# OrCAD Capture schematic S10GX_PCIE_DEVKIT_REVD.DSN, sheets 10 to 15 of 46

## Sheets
10 S10 GX Bank 3I,J,K,L: size C
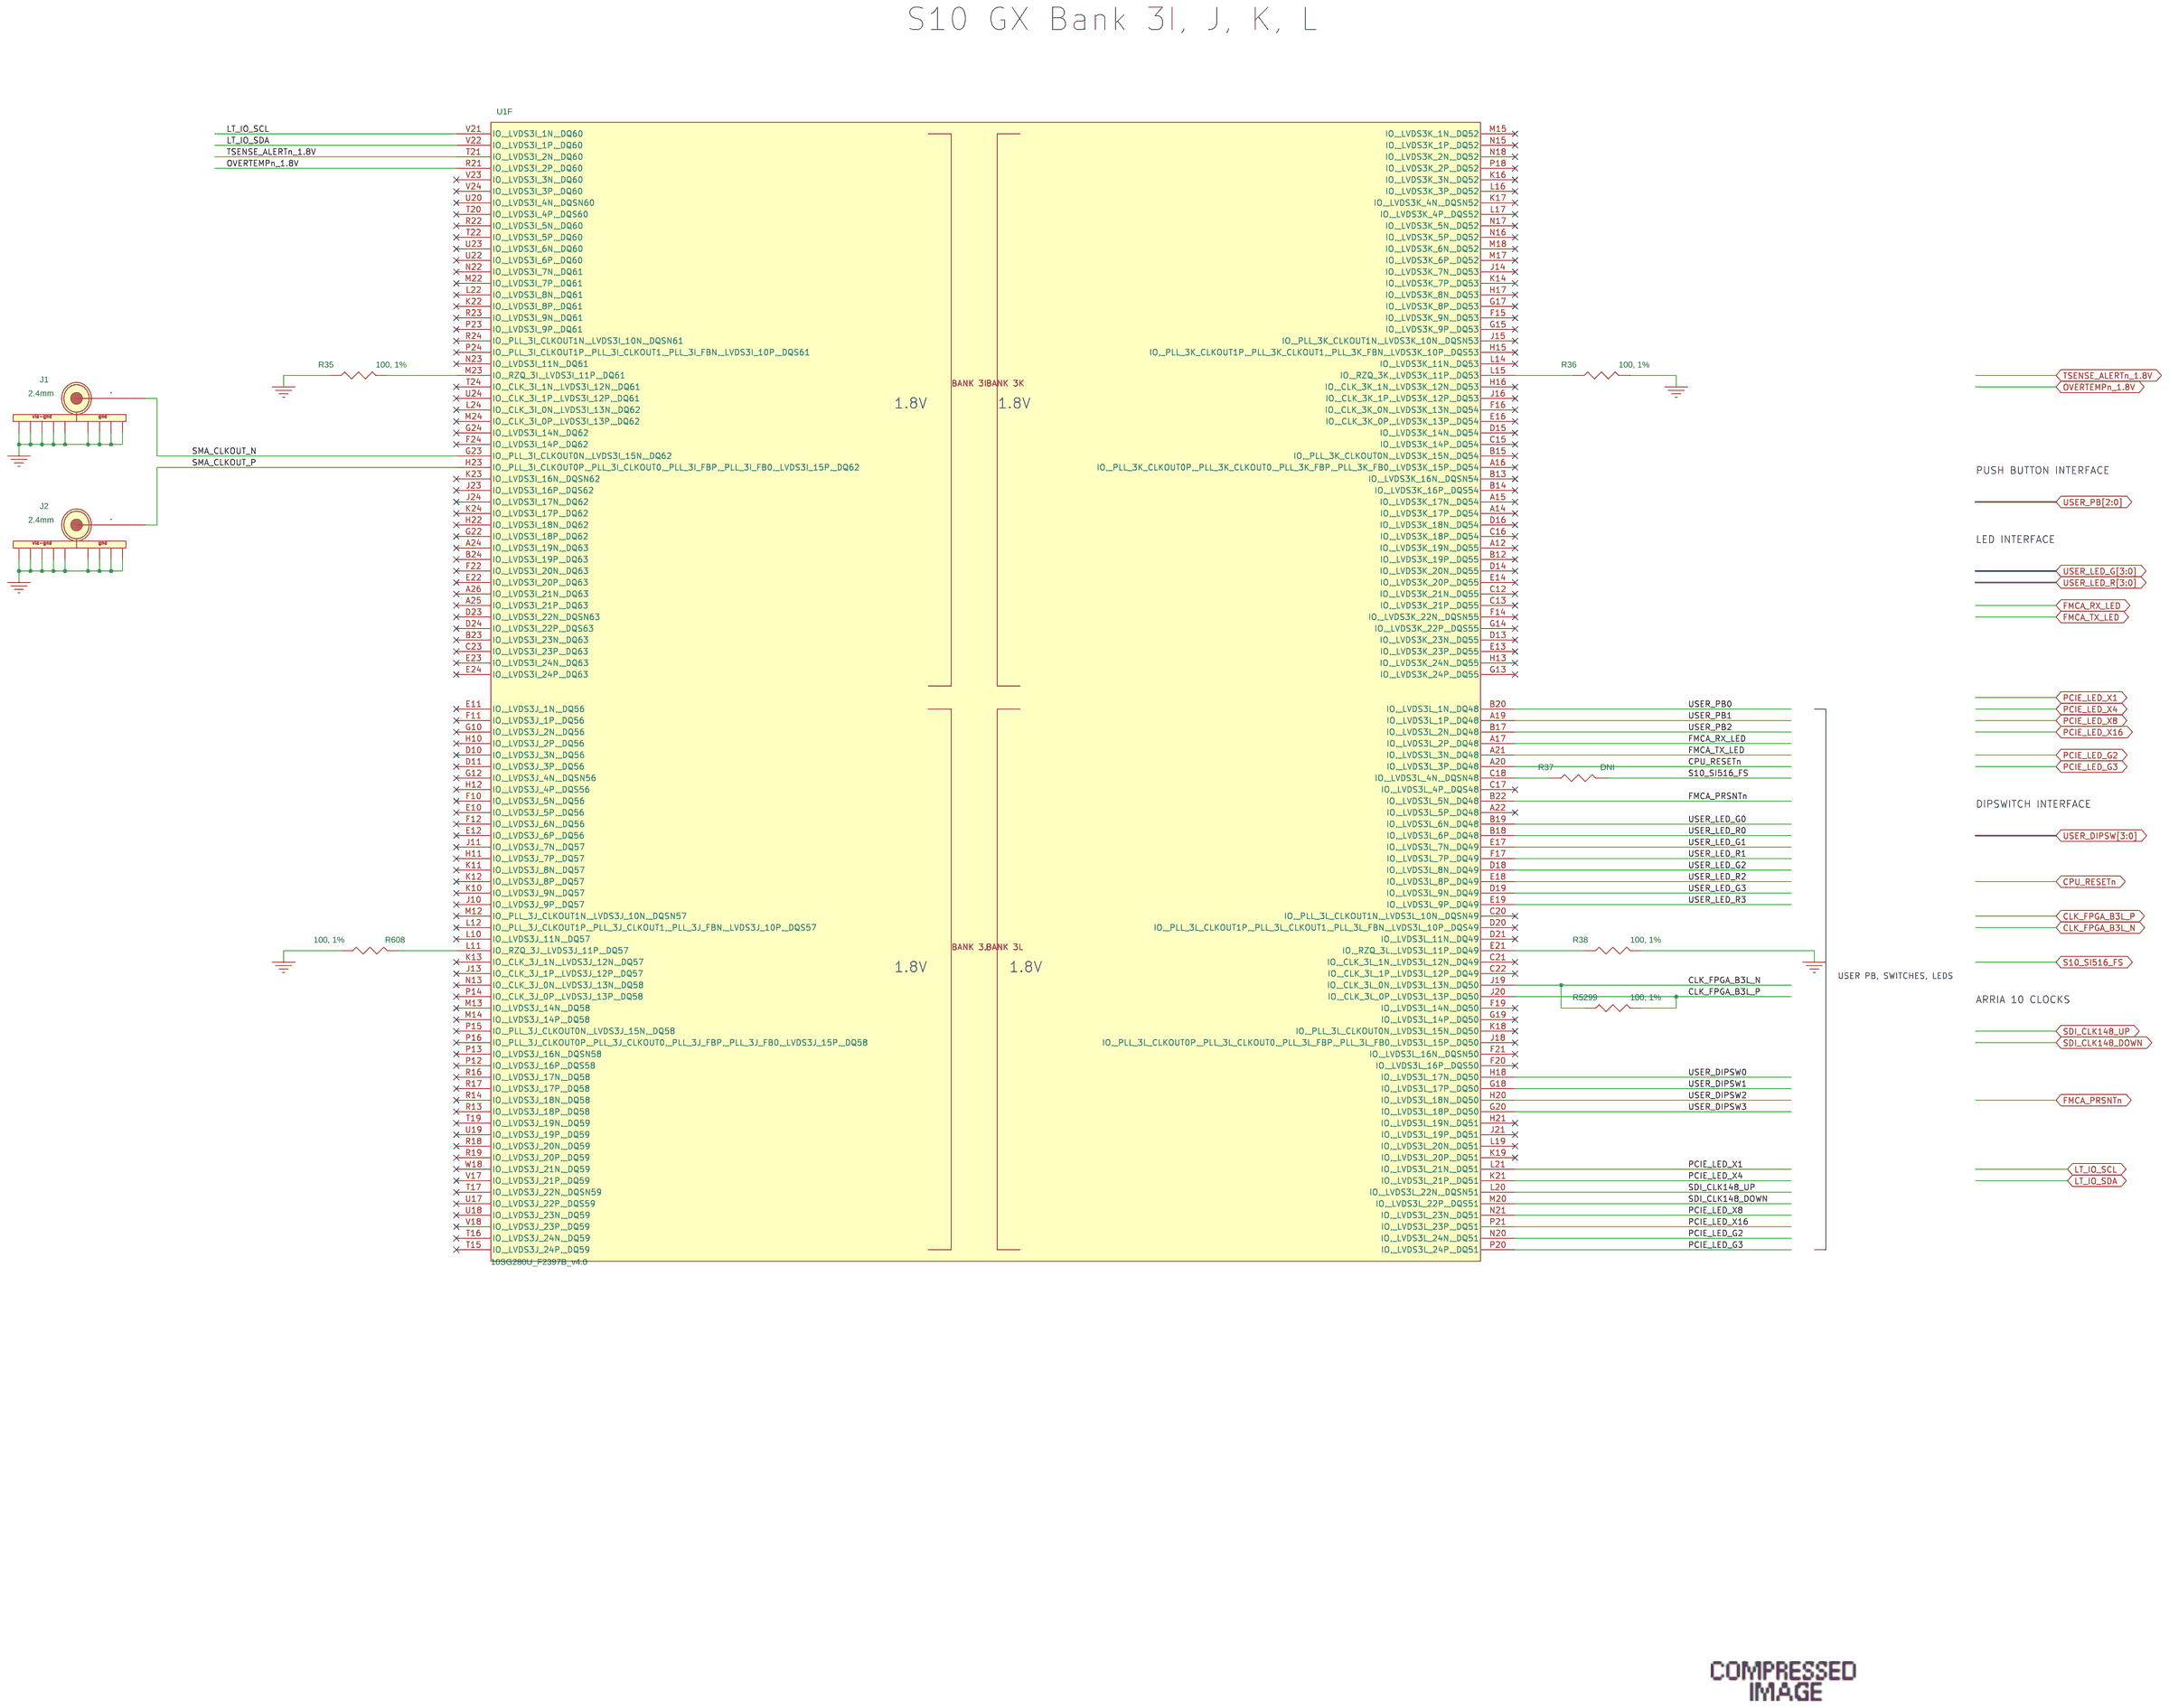
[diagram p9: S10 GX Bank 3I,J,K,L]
11 S10 GX Xcvr GXBL 1C,D,E,F: size C
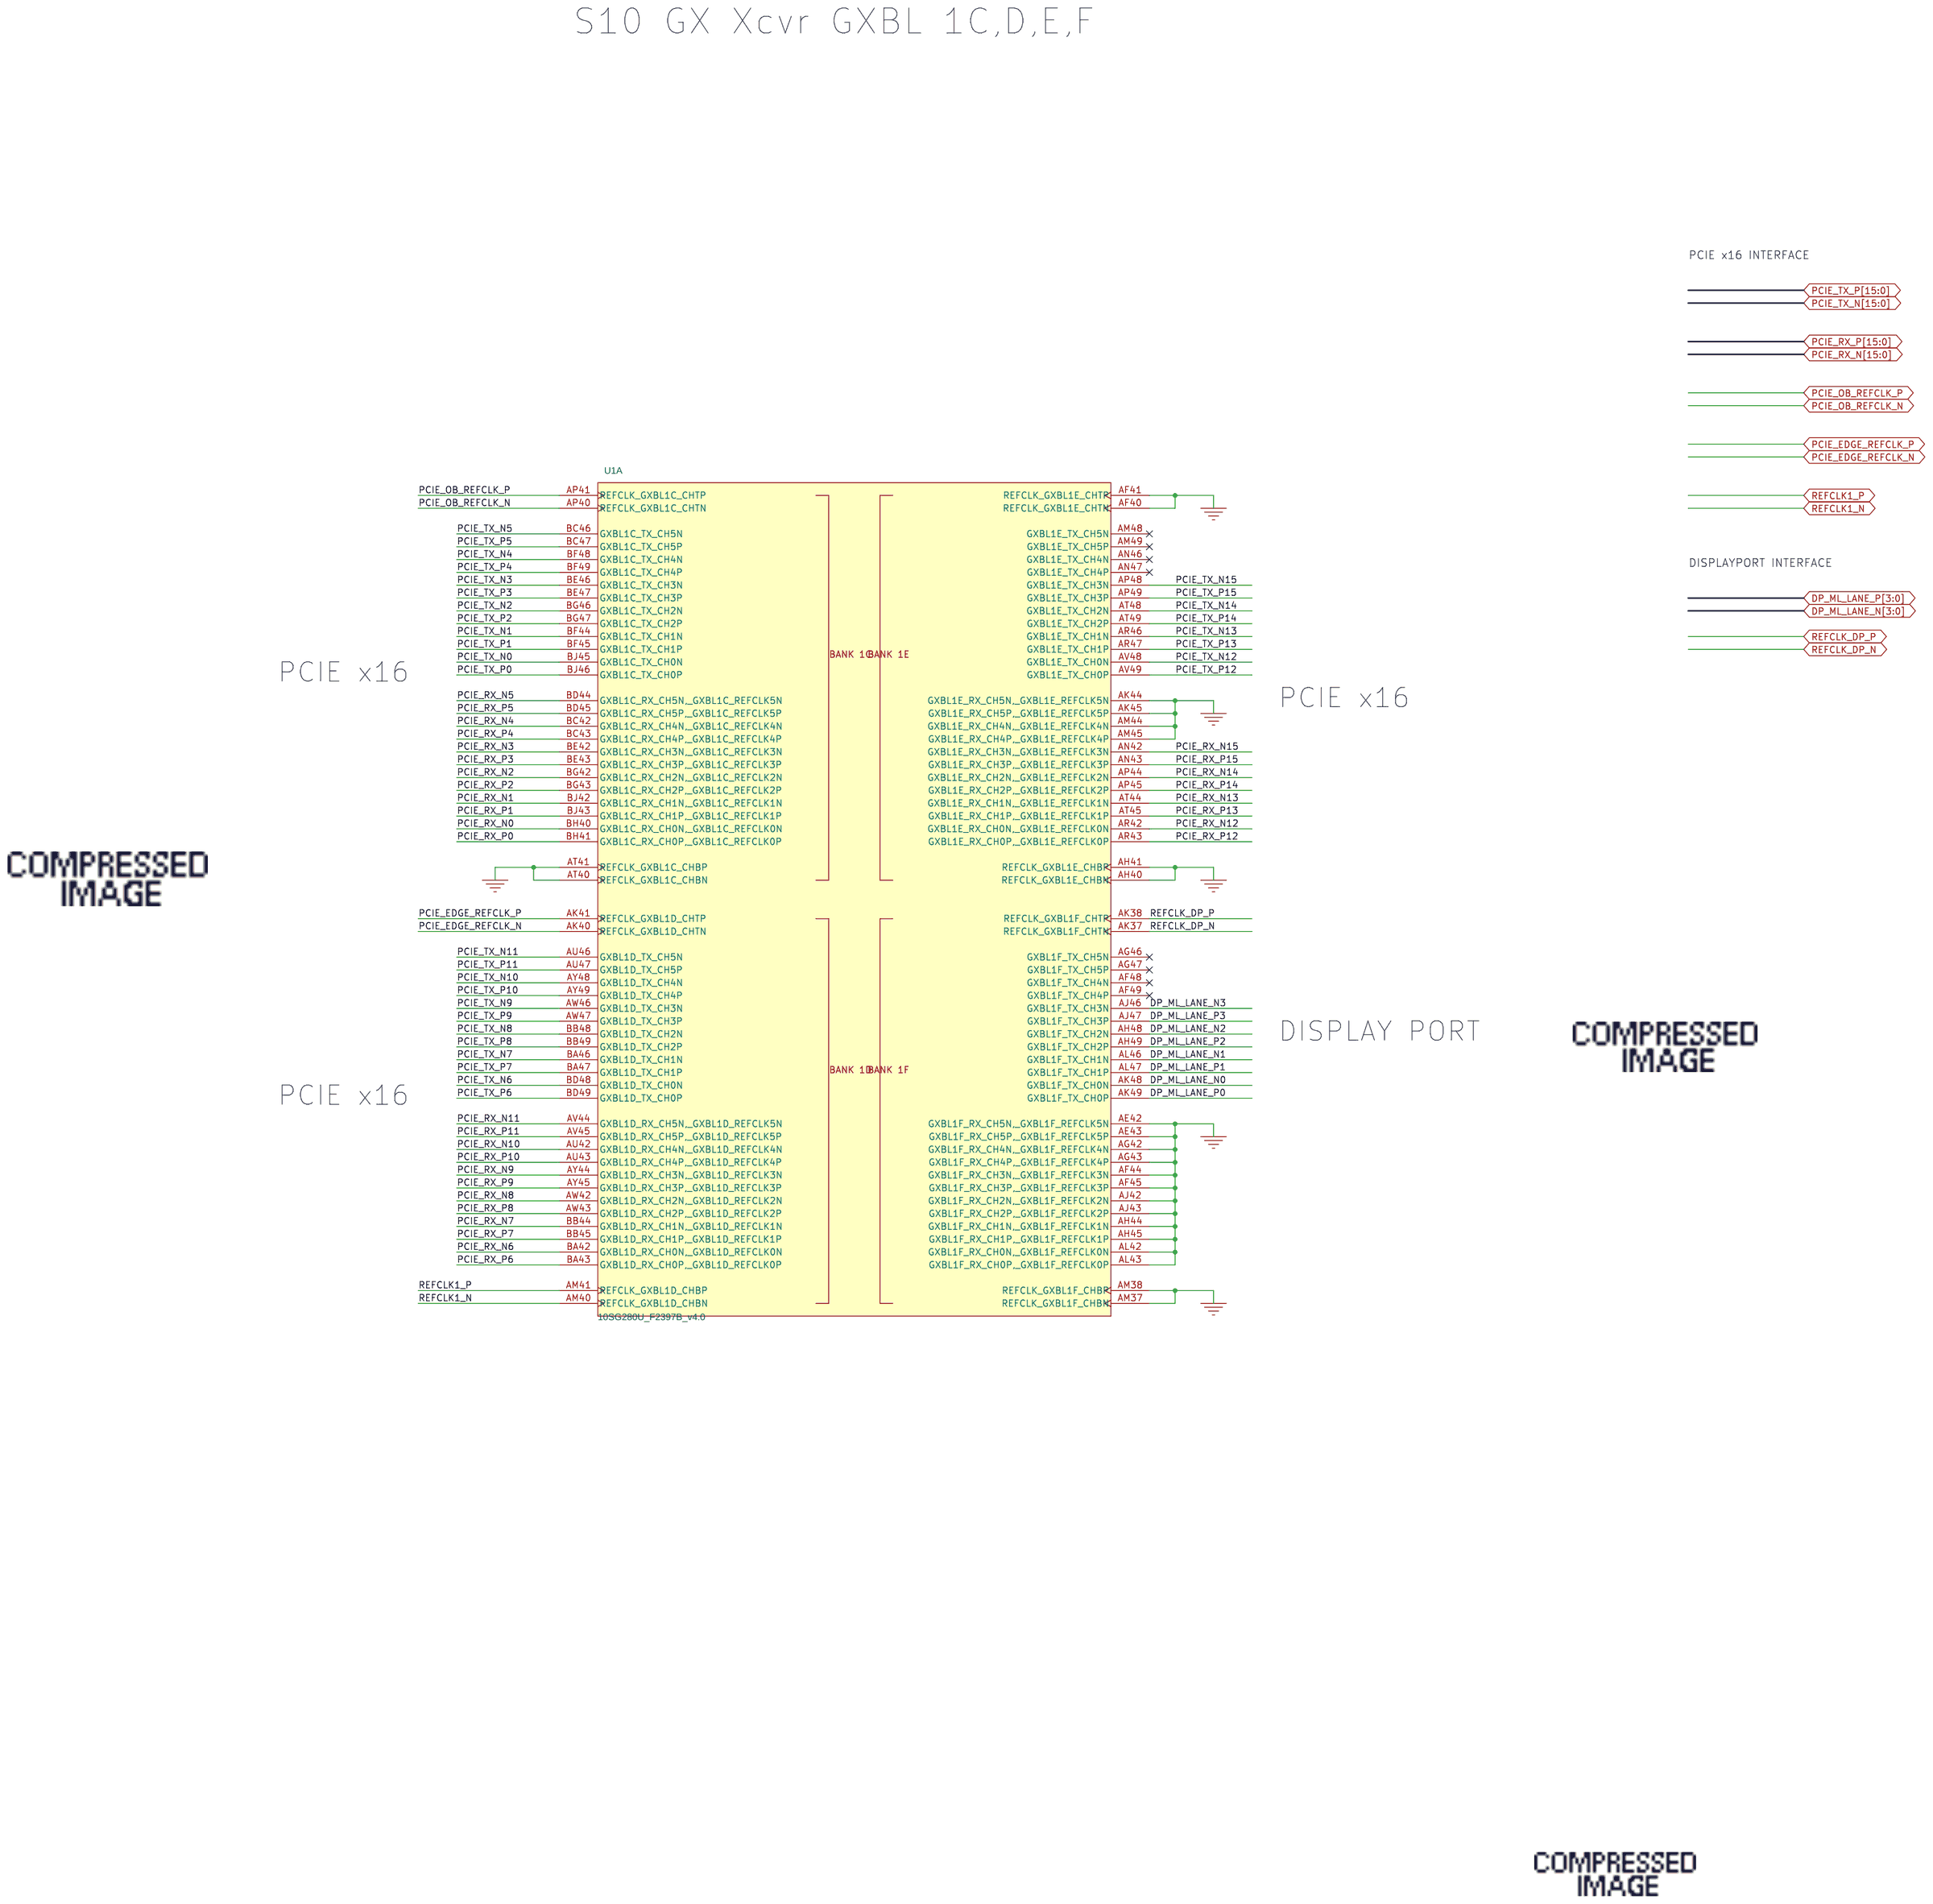
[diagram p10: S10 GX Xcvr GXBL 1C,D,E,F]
12 S10 GX Xcvr GXBL 1K,L,M,N: size C
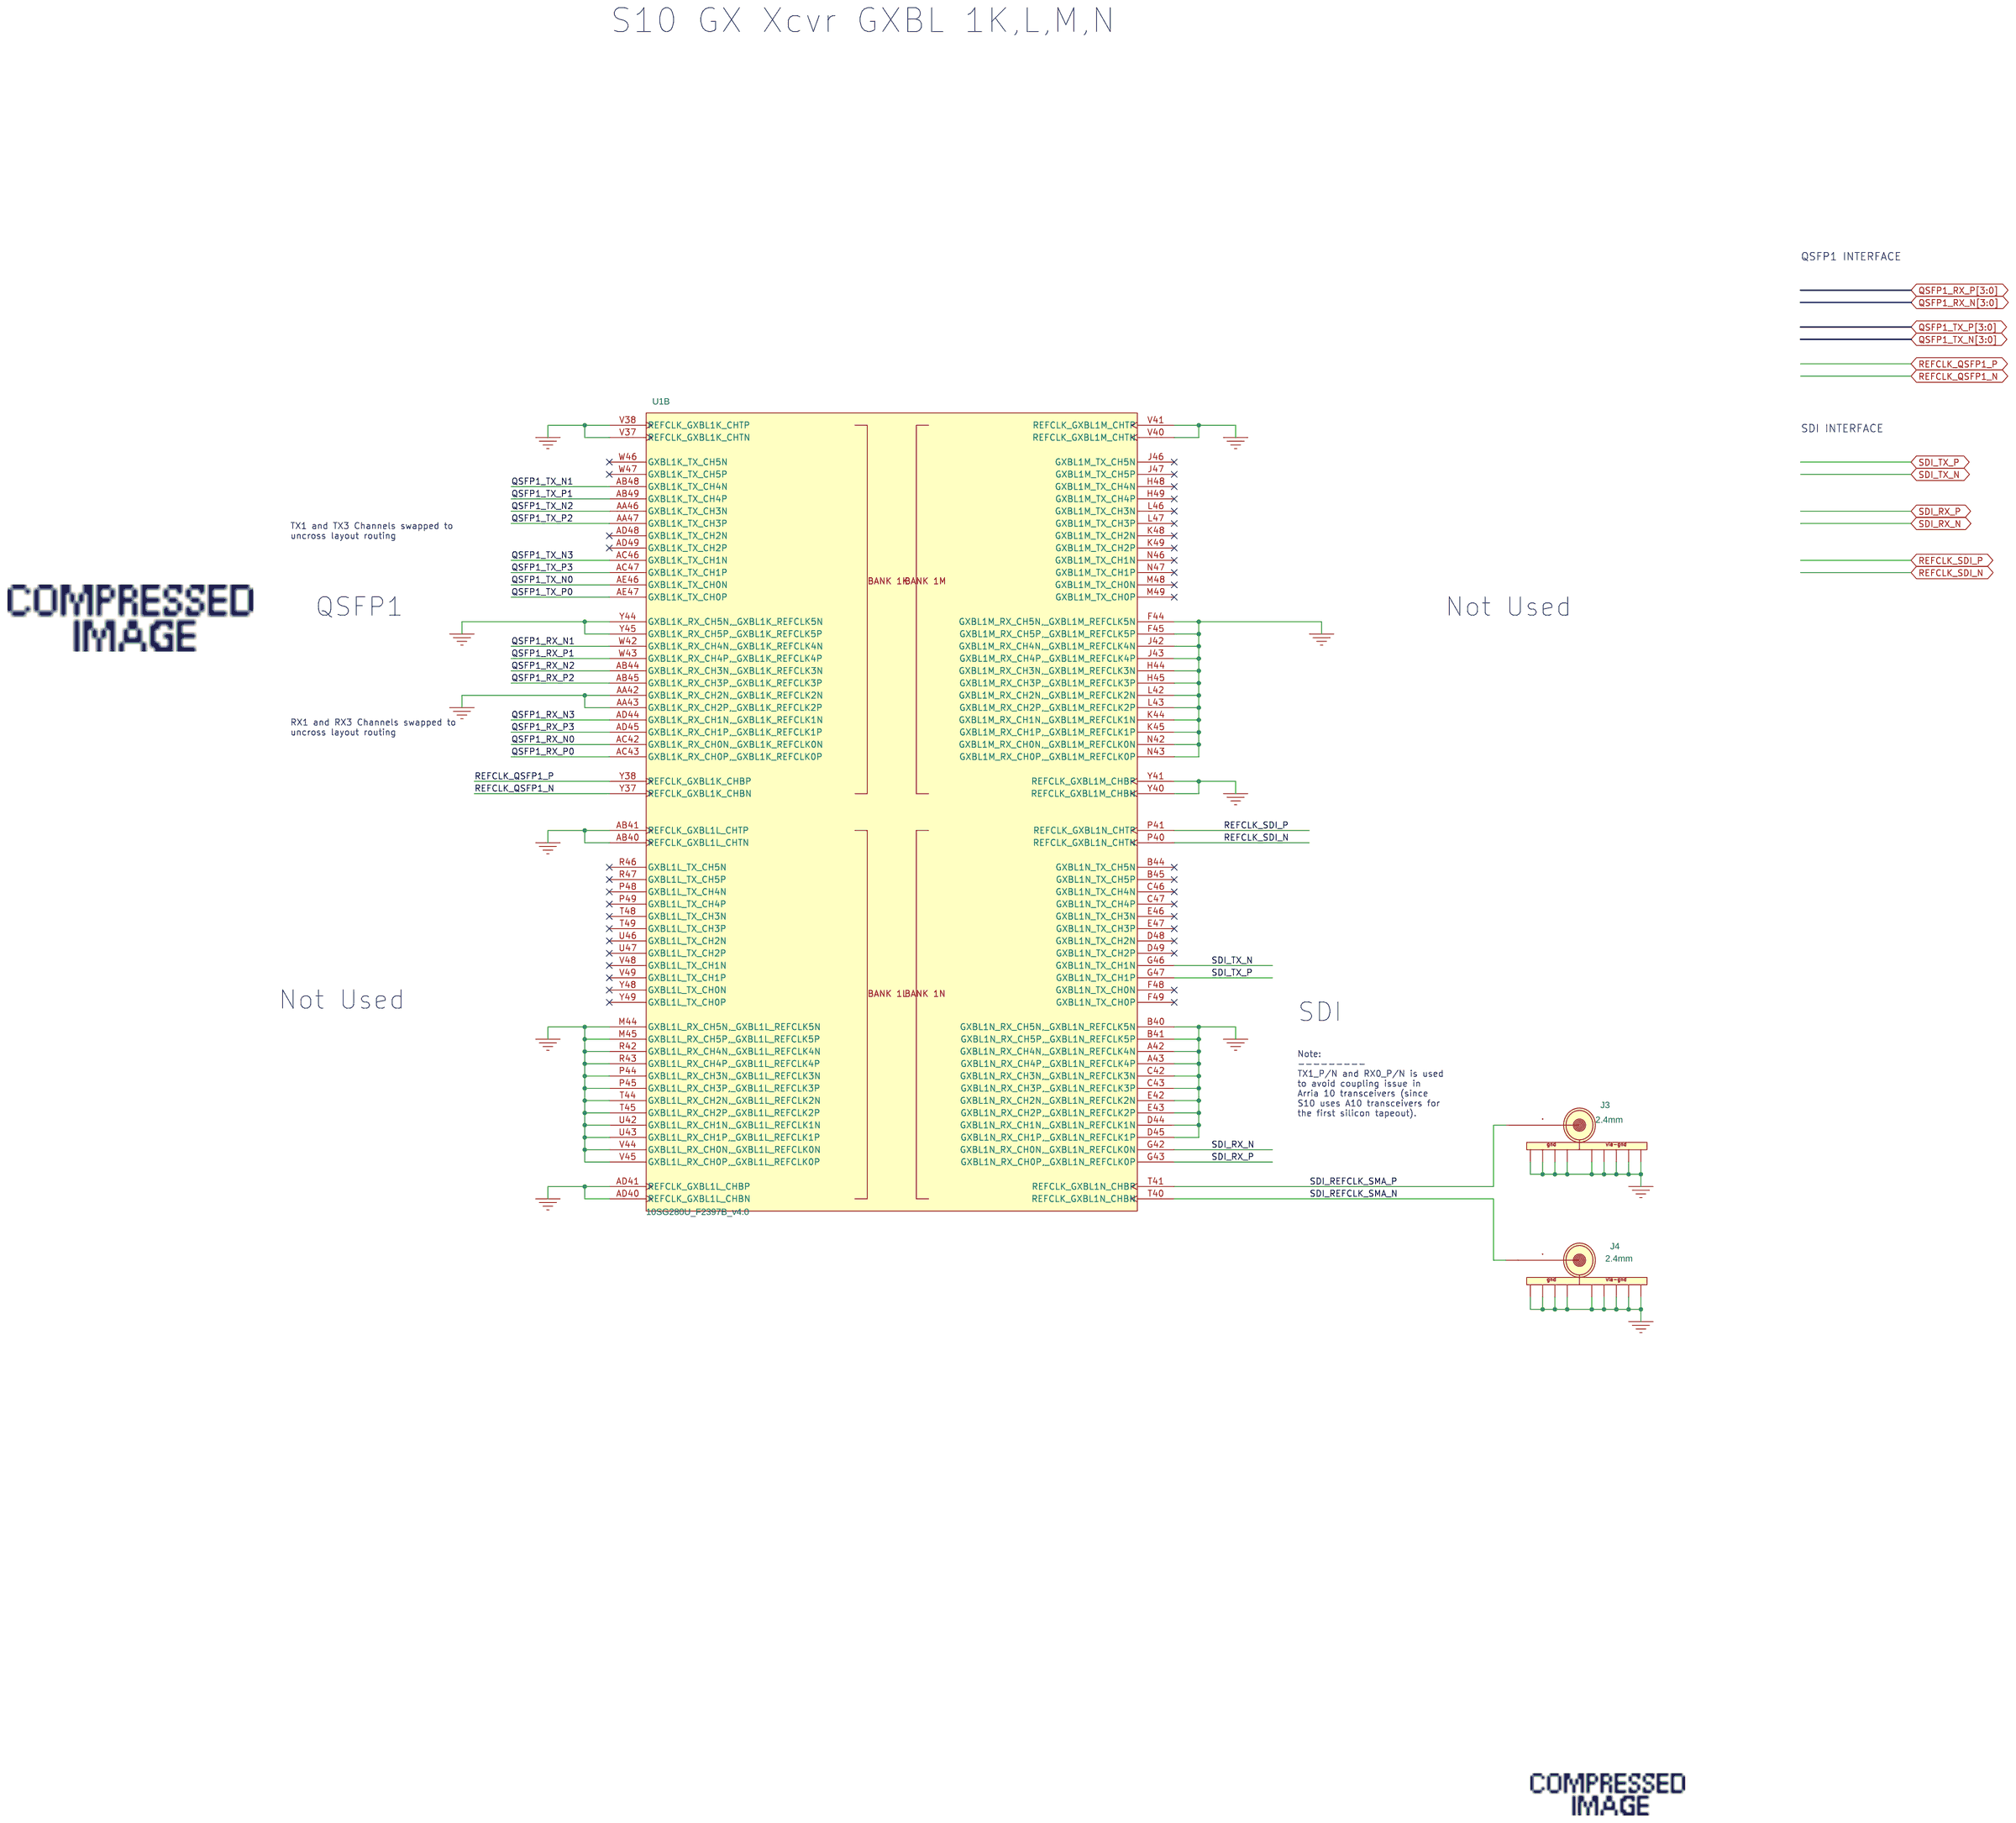
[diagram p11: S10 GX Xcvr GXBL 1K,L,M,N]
13 S10 GX Xcvr GXBR 4C,D,E,F: size C
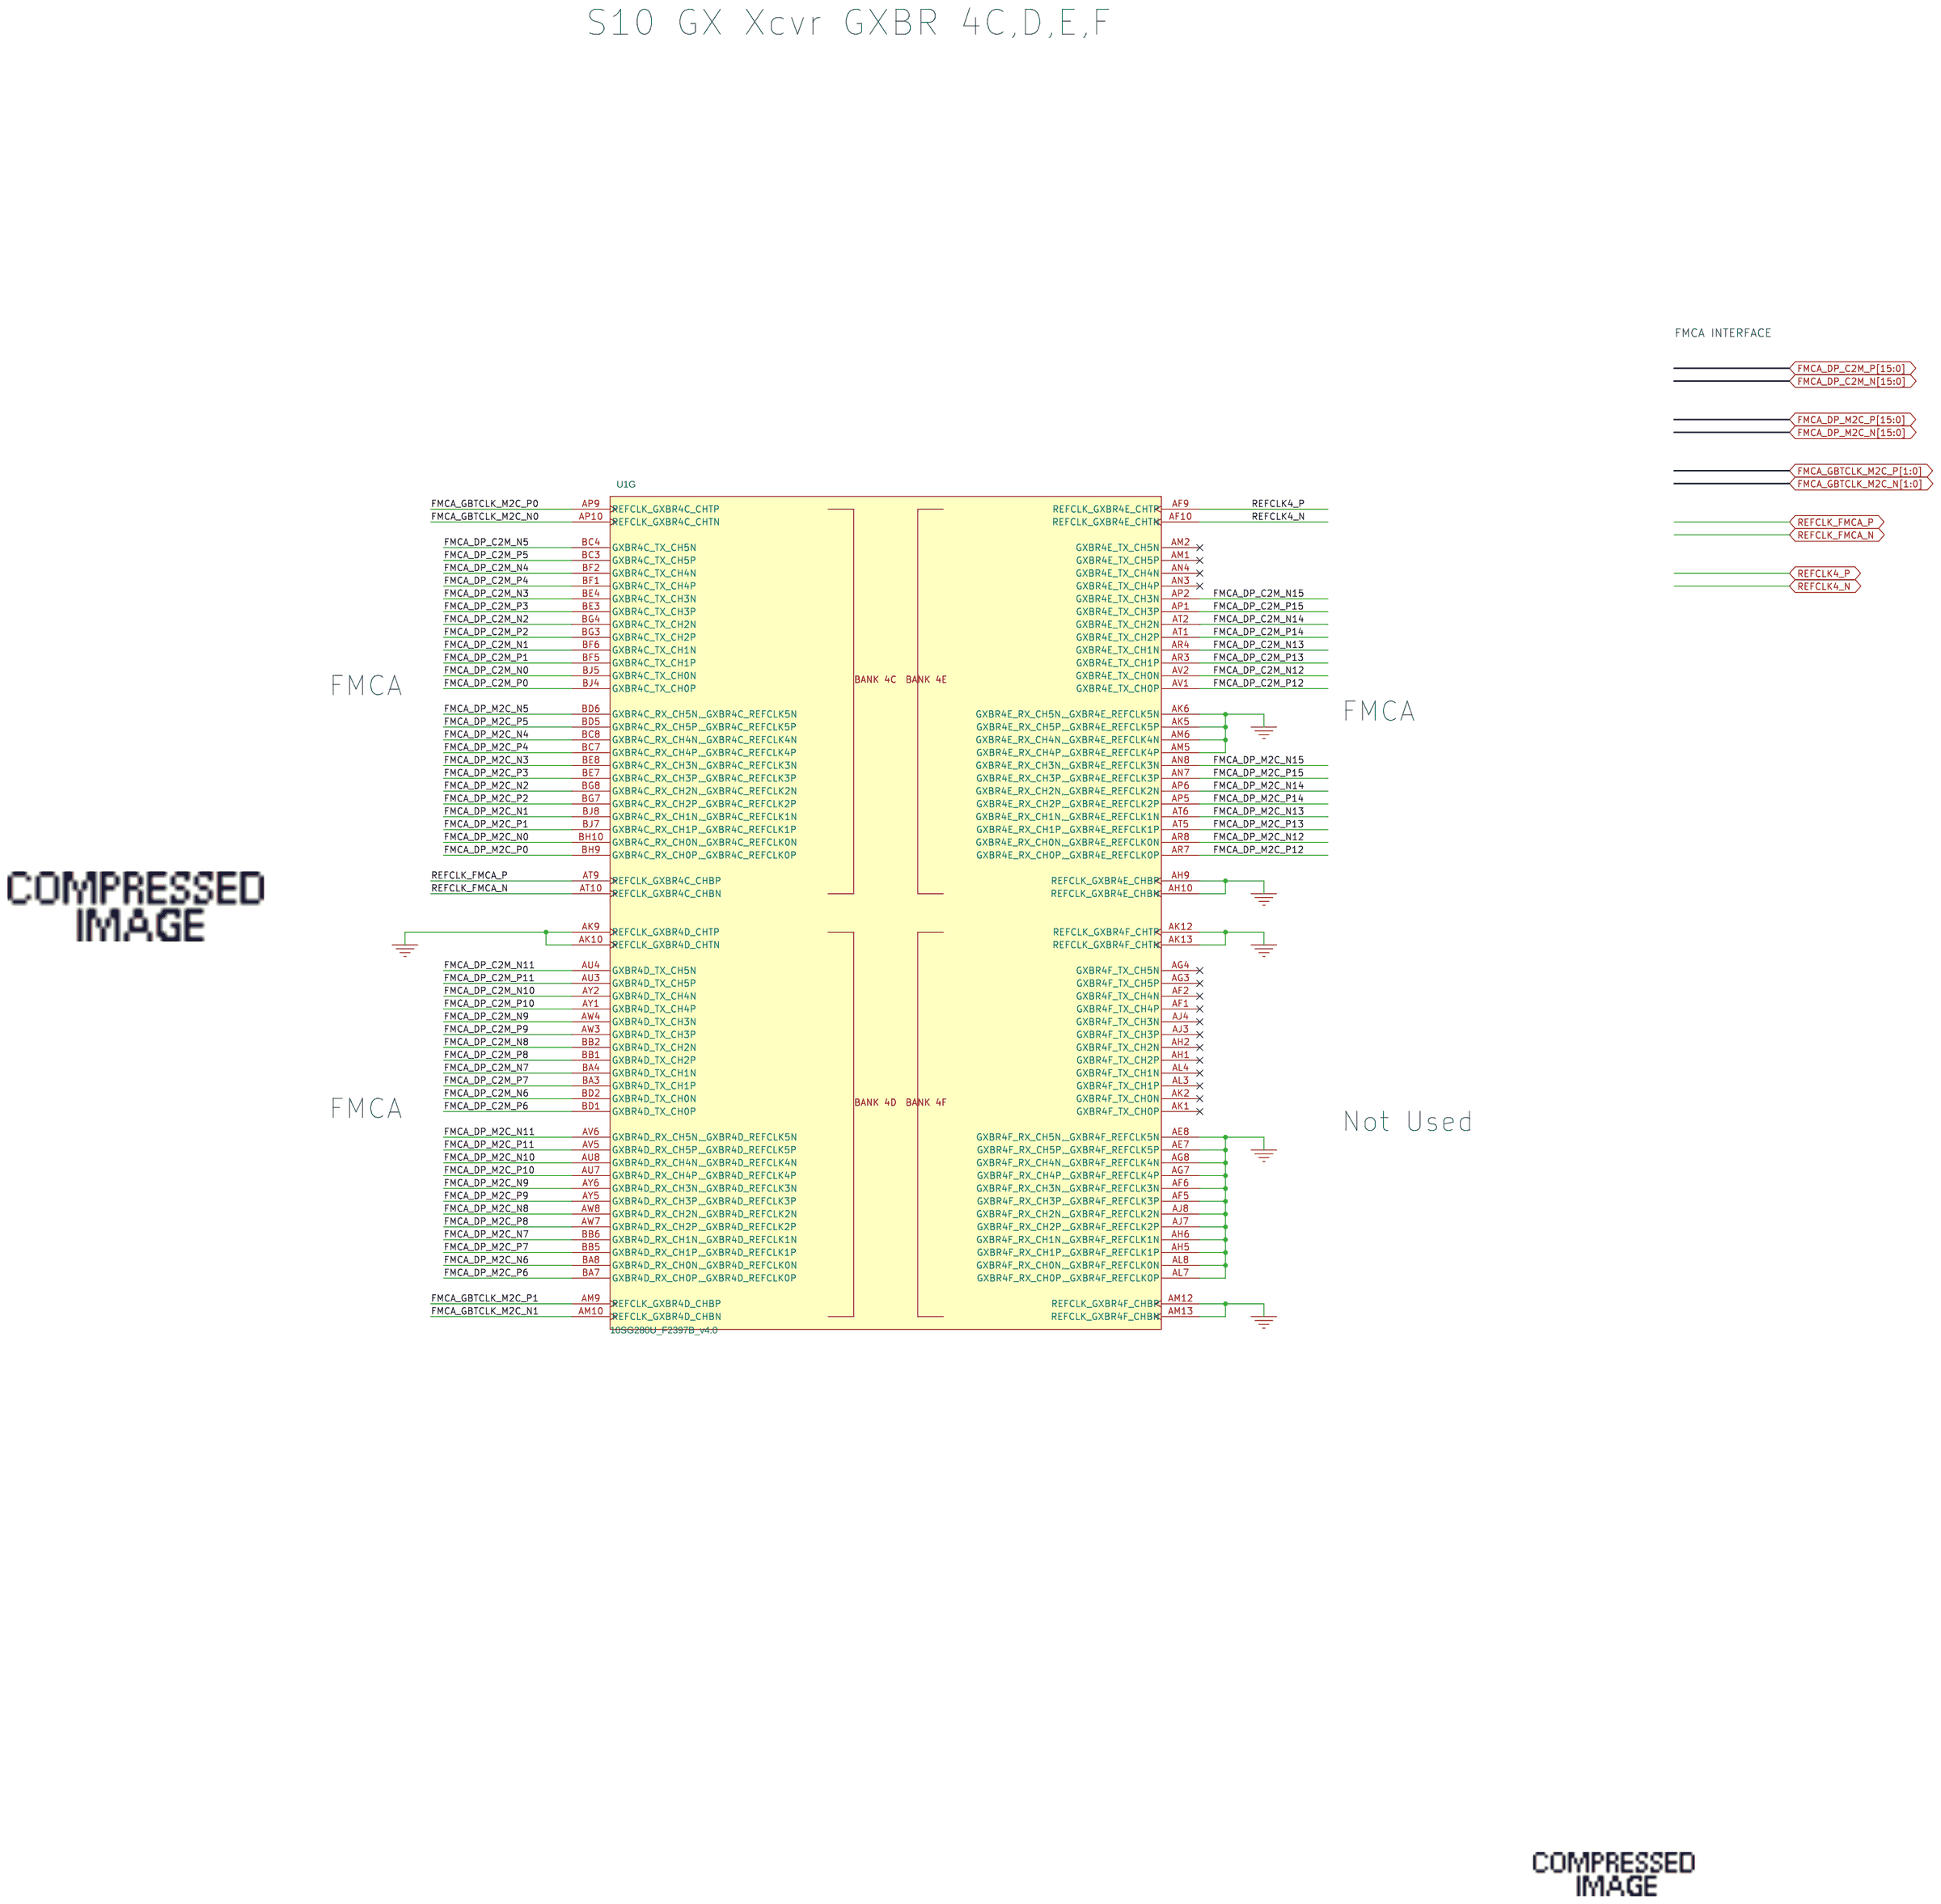
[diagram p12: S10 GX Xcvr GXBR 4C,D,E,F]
14 S10 GX Xcvr GXBR 4K,L,M,N: size C
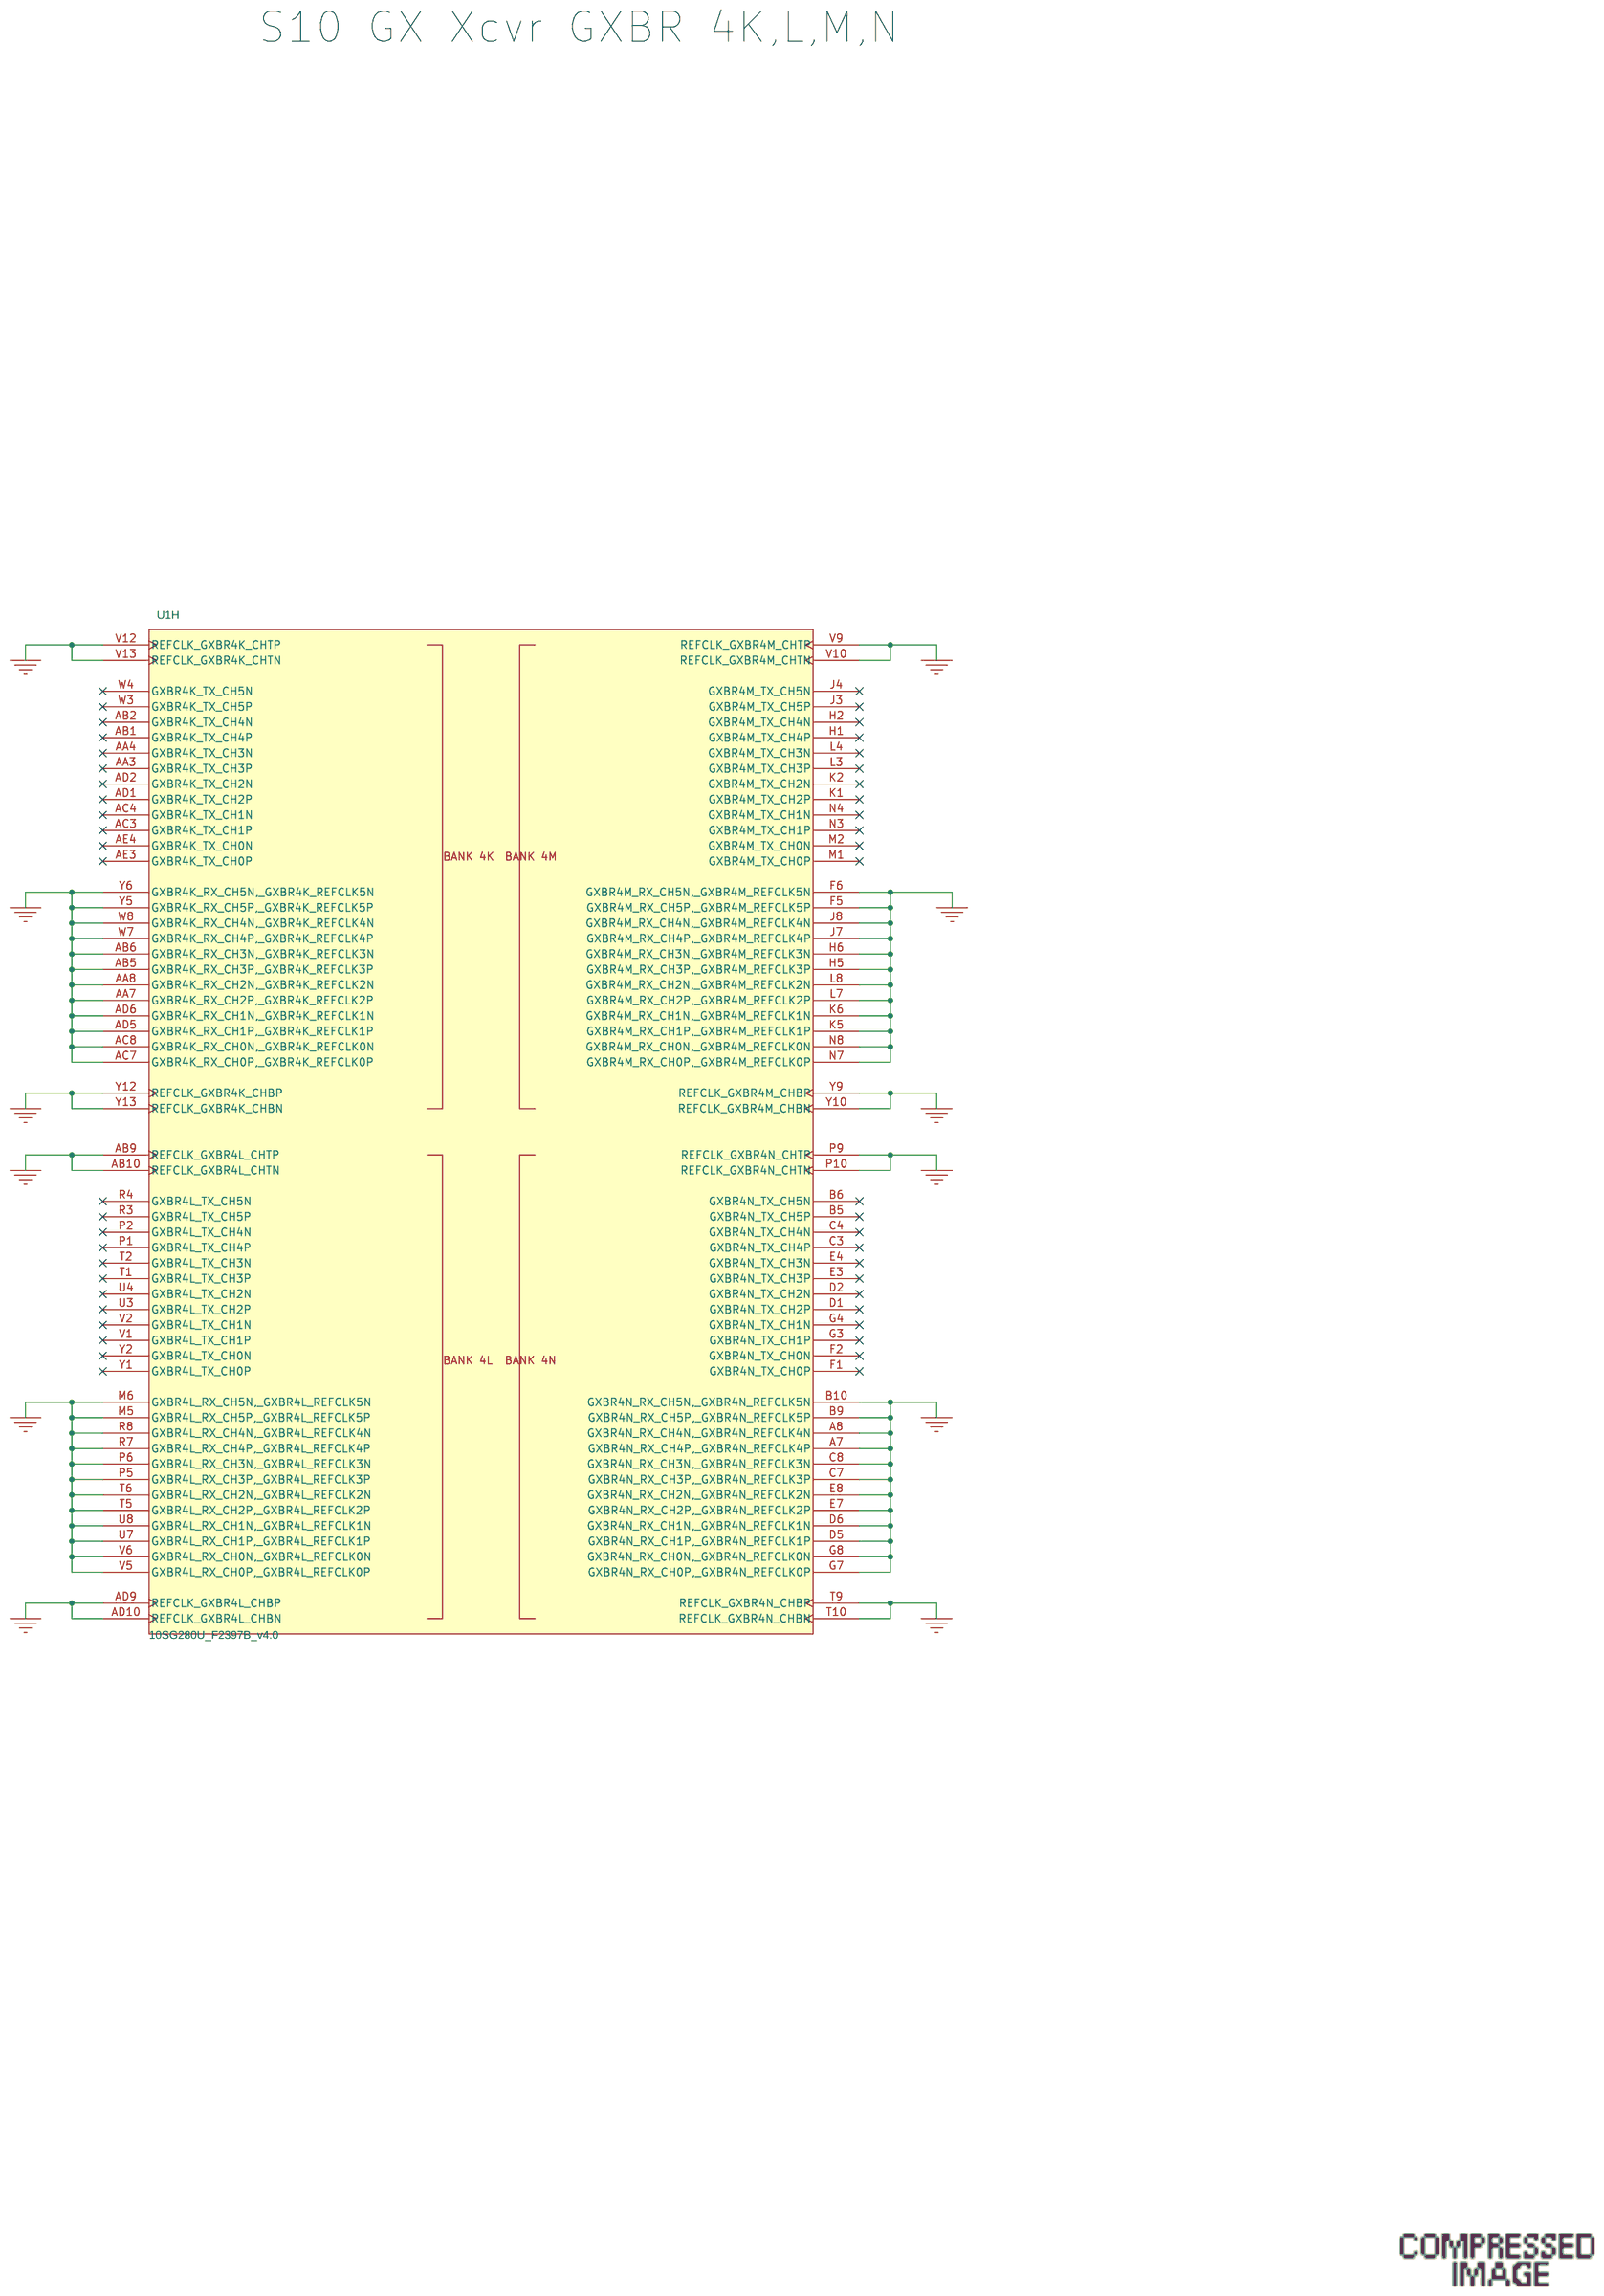
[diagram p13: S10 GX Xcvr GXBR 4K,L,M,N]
15 S10 GX Power: size C
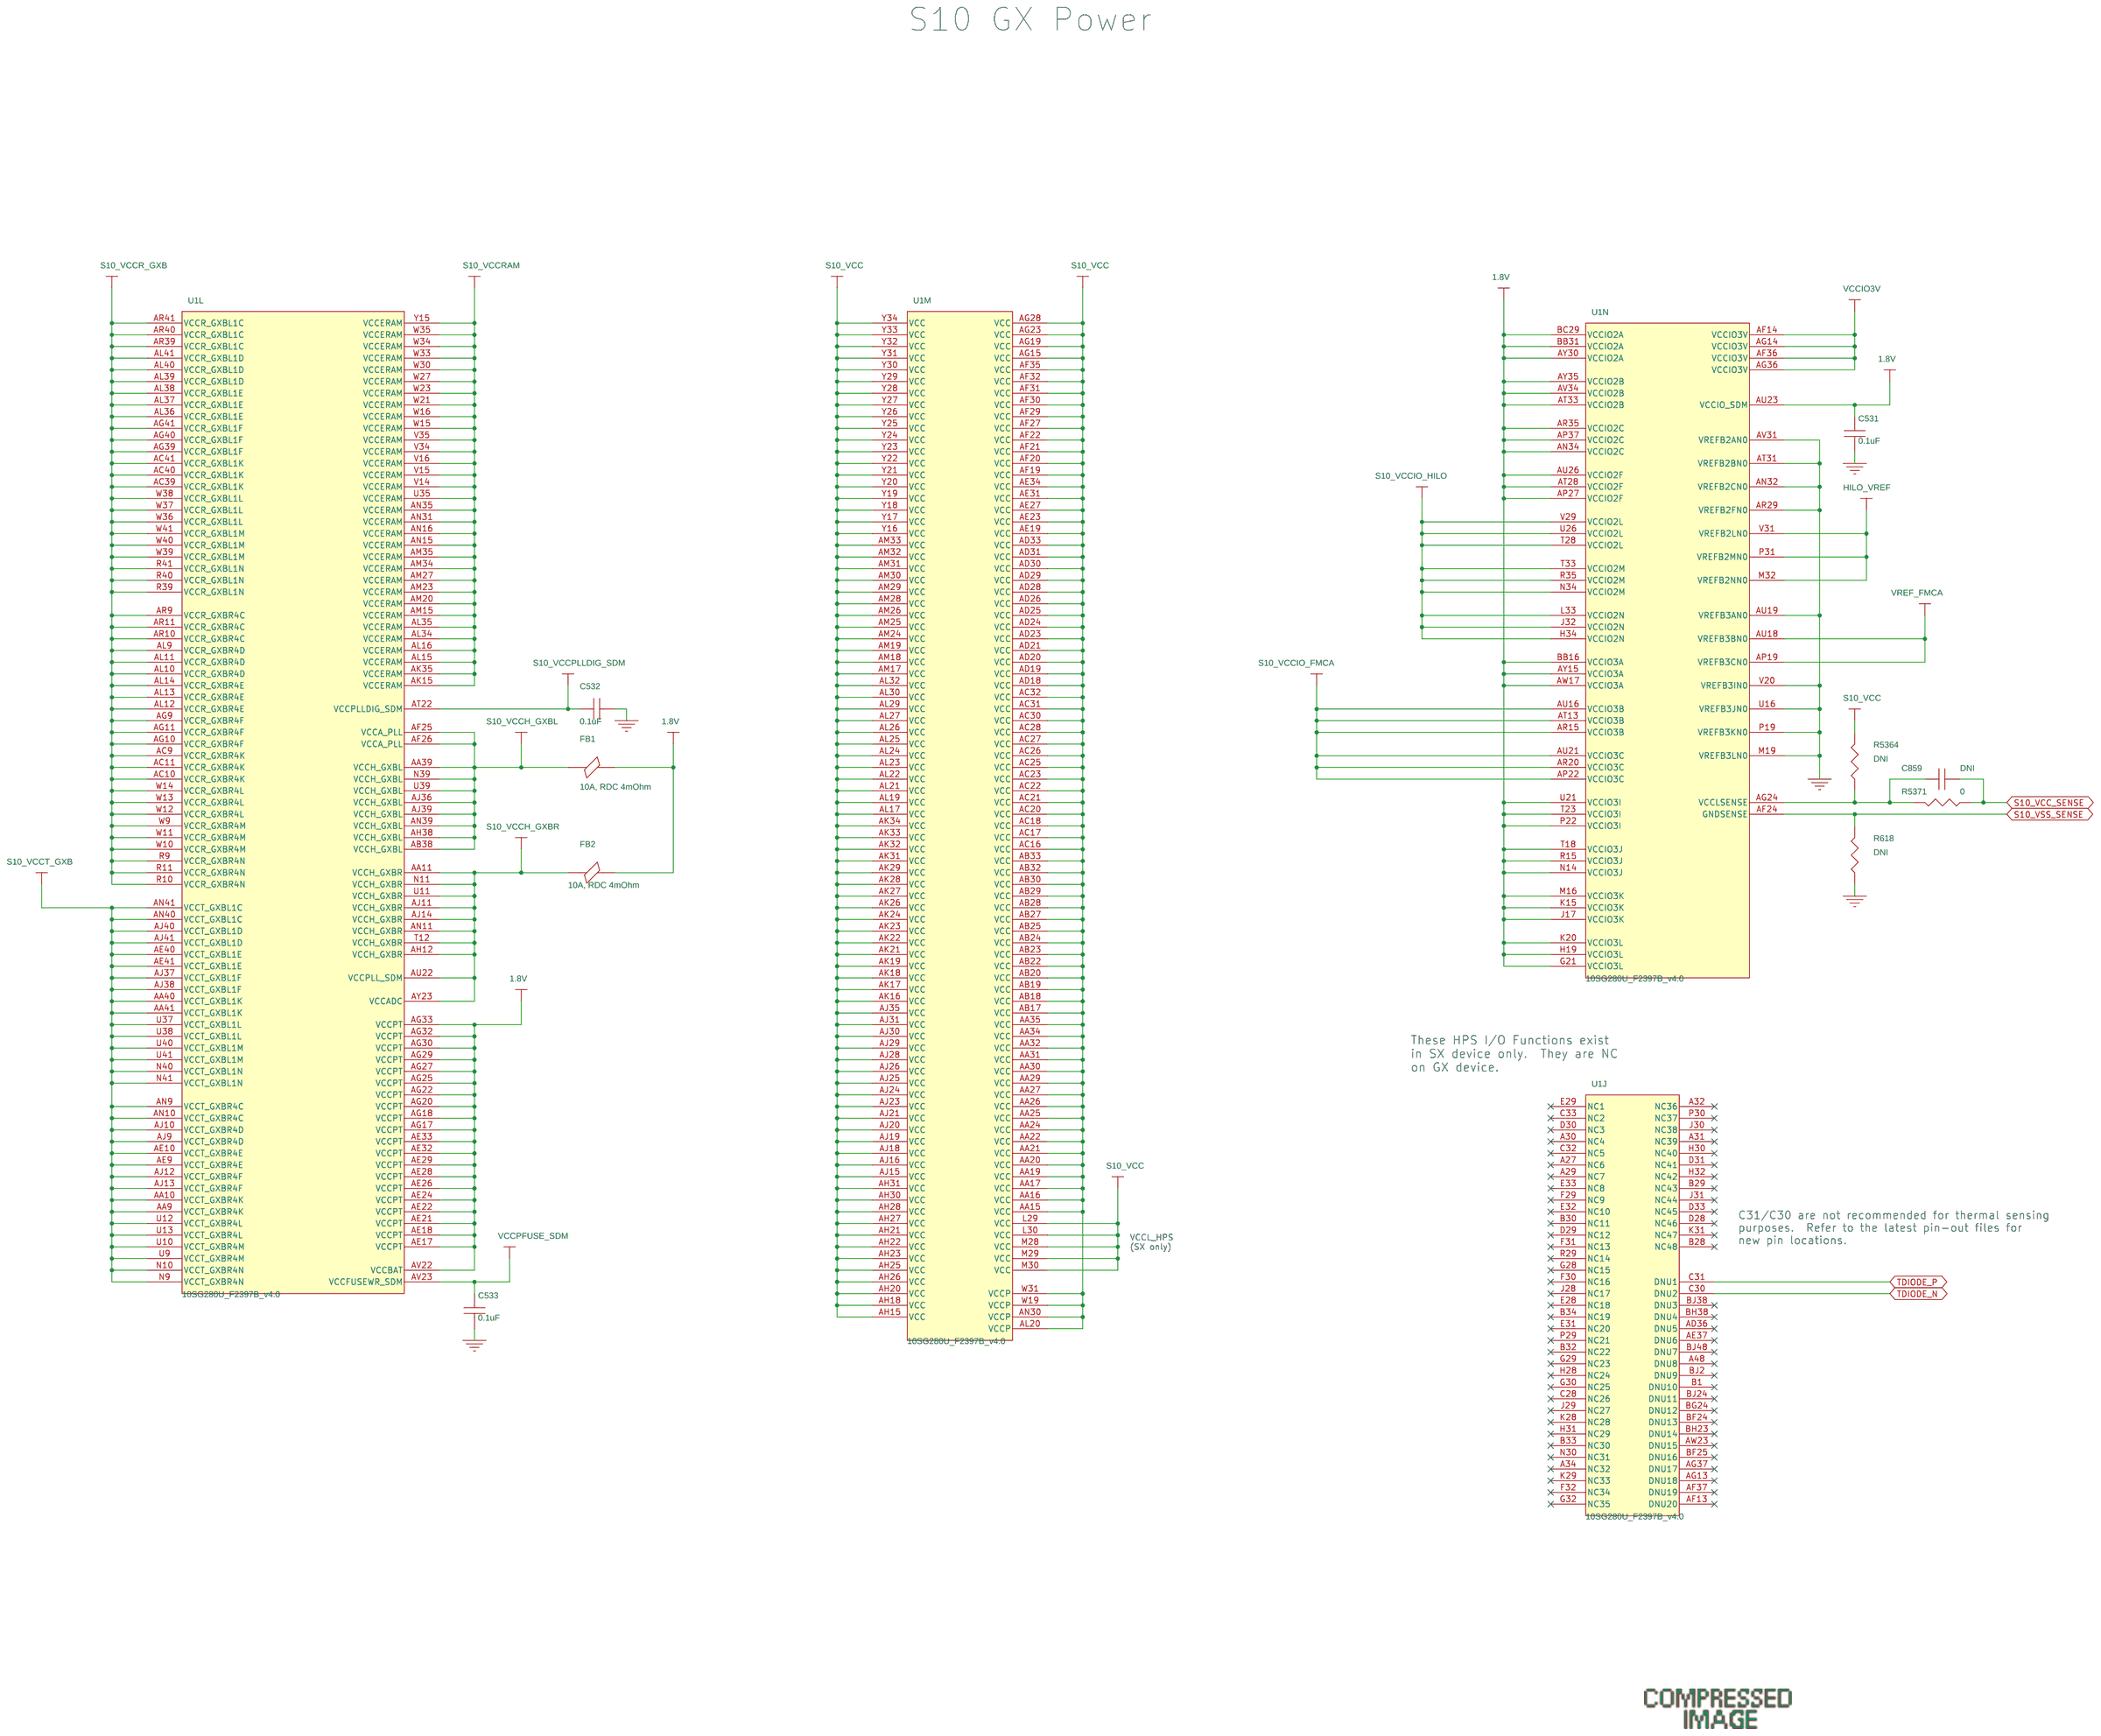
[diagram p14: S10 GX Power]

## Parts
sheet S10 GX Bank 3I,J,K,L
J1  2.4mm  [96-MMPX-50-0-1]
J2  2.4mm  [96-MMPX-50-0-1]
R35  100, 1%  [0402]
R36  100, 1%  [0402]
R37  DNI  [0402]
R38  100, 1%  [0402]
R608  100, 1%  [0402]
R5299  100, 1%  [0402]
sheet S10 GX Configuration
U1  10SG280U_F2397B_v4.0  [BGA_F2397B]  (sections A,B,C,D,E,F,G,H,I,J,K,L,M,N,O,P,Q,R,S)
sheet S10 GX Power
C531  0.1uF  [0402]
C532  0.1uF  [0402]
C533  0.1uF  [0402]
C859  DNI  [0402]
FB1  10A, RDC 4mOhm  [IND_WURTH_74279223560]
FB2  10A, RDC 4mOhm  [IND_WURTH_74279223560]
R618  DNI  [0402]
R5364  DNI  [0402]
R5371  0  [0402]
sheet S10 GX Xcvr GXBL 1K,L,M,N
J3  2.4mm  [96-MMPX-50-0-1]
J4  2.4mm  [96-MMPX-50-0-1]

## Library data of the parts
J1-J4 = SMA-2.4mm
R35 R36 R38 R608 R5299 = RESISTOR: RES,100 OHMS,1.0%,1/16W,0402; Item Num: P02-11381R; Lead Free Status: No; Manufacturer: Panasonic; Manufacturer Part Num: ERJ-2RKF1000X; Num Pins: 2; Part Class: Resistors; Price: 0; RoHS Compliant: Yes; Tolerance: 1%
R37 R618 R5364 = RESISTOR: RES ZERO OHM 1/16W 5% 0402 SMD; Altera Part No.: P02-14020R; Item Num: P02-14020R; Lead Free Status: No; Manufacturer: Panasonic; Manufacturer Part Num: ERJ-2GE0R00X; Num Pins: 2; Part Class: RESISTORS; Price: 0; RoHS Compliant: Yes; Tolerance: 5%
U1 = 10SG280U_F2397B_v4_1.0
C531-C533 = CAP: CAP - CERAMIC,  0.1UF 0402 25VDC Y5V; Dielectric: X5R; Item Num: P03-15057R; LIFECYCLE_PHASE: Active; Lead Free Status: Lead Free; Manufacturer: Murata; Manufacturer Part Num: GRM155F51E104ZA01D; Num Pins: 2; Part Class: CAPACITORS; Price: 0.07; RoHS Compliant: RoHS Compliant; Tolerance: +80%/-20%
C859 = CAP: CAP - CERAMIC,  0.1UF 0402 25VDC Y5V; CAPACITANCE: 0.1uF; Dielectric: X5R; Item Num: P03-15057R; LIFECYCLE_PHASE: Active; Lead Free Status: Lead Free; Manufacturer: Murata; Manufacturer Part Num: GRM155F51E104ZA01D; Num Pins: 2; Part Class: CAPACITORS; Price: 0.07; RoHS Compliant: RoHS Compliant; Tolerance: +80%/-20%
FB1 FB2 = BEAD_FERRITE_SM: ND - FERRITE BEAD, 56 OHM@100MHZ, RDC 0.004-OHM, 10A, SMD 1612; Item Num: P04-17100R; LIFECYCLE_PHASE: Active; MFR_LIFECYCLE: Active; Manufacturer: Wurth Elektronik; Manufacturer Part Num: 74279223560; Num Pins: 2; PART_SUBCLASS: INDUCTORS; Part Class: Inductors; RoHS Compliant: Yes
R5371 = RESISTOR: RES ZERO OHM 1/16W 5% 0402 SMD; Altera Part No.: P02-14020R; Item Num: P02-14020R; Lead Free Status: No; Manufacturer: Panasonic; Manufacturer Part Num: ERJ-2GE0R00X; Num Pins: 2; Part Class: RESISTORS; RoHS Compliant: Yes; Tolerance: 5%

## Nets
1.8V: C531.1 FB1.1 FB2.1 U1.AE17(VCCPT) U1.AE18(VCCPT) U1.AE21(VCCPT) U1.AE22(VCCPT) U1.AE24(VCCPT) U1.AE26(VCCPT) U1.AE28(VCCPT) U1.AE29(VCCPT) U1.AE32(VCCPT) U1.AE33(VCCPT) U1.AG17(VCCPT) U1.AG18(VCCPT) U1.AG20(VCCPT) U1.AG22(VCCPT) U1.AG25(VCCPT) U1.AG27(VCCPT) U1.AG29(VCCPT) U1.AG30(VCCPT) U1.AG32(VCCPT) U1.AG33(VCCPT) U1.AN34(VCCIO2C) U1.AP27(VCCIO2F) U1.AP37(VCCIO2C) U1.AR35(VCCIO2C) U1.AT28(VCCIO2F) U1.AT33(VCCIO2B) U1.AU23(VCCIO_SDM) U1.AU26(VCCIO2F) U1.AV22(VCCBAT) U1.AV34(VCCIO2B) U1.AW17(VCCIO3A) U1.AY15(VCCIO3A) U1.AY30(VCCIO2A) U1.AY35(VCCIO2B) U1.BB16(VCCIO3A) U1.BB31(VCCIO2A) U1.BC29(VCCIO2A) U1.G21(VCCIO3L) U1.H19(VCCIO3L) U1.J17(VCCIO3K) U1.K15(VCCIO3K) U1.K20(VCCIO3L) U1.M16(VCCIO3K) U1.N14(VCCIO3J) U1.P22(VCCIO3I) U1.R15(VCCIO3J) U1.T18(VCCIO3J) U1.T23(VCCIO3I) U1.U21(VCCIO3I) ; also on sheet 6 9 16 17 19 20 24 27 28 29 30 31 39 45
GND: C531.2 C532.2 C533.2 J1.2 J1.3 J1.4 J1.5 J1.6 J1.7 J1.8 J1.9 J1.10 J2.2 J2.3 J2.4 J2.5 J2.6 J2.7 J2.8 J2.9 J2.10 J3.2 J3.3 J3.4 J3.5 J3.6 J3.7 J3.8 J3.9 J3.10 J4.2 J4.3 J4.4 J4.5 J4.6 J4.7 J4.8 J4.9 J4.10 R35.1 R36.2 R38.2 R608.2 R618.1 U1.A7(GXBR4N_RX_CH4P,_GXBR4N_REFCLK4P) U1.A8(GXBR4N_RX_CH4N,_GXBR4N_REFCLK4N) U1.A42(GXBL1N_RX_CH4N,_GXBL1N_REFCLK4N) U1.A43(GXBL1N_RX_CH4P,_GXBL1N_REFCLK4P) U1.AA7(GXBR4K_RX_CH2P,_GXBR4K_REFCLK2P) U1.AA8(GXBR4K_RX_CH2N,_GXBR4K_REFCLK2N) U1.AA42(GXBL1K_RX_CH2N,_GXBL1K_REFCLK2N) U1.AA43(GXBL1K_RX_CH2P,_GXBL1K_REFCLK2P) U1.AB5(GXBR4K_RX_CH3P,_GXBR4K_REFCLK3P) U1.AB6(GXBR4K_RX_CH3N,_GXBR4K_REFCLK3N) U1.AB9(REFCLK_GXBR4L_CHTP) U1.AB10(REFCLK_GXBR4L_CHTN) U1.AB40(REFCLK_GXBL1L_CHTN) U1.AB41(REFCLK_GXBL1L_CHTP) U1.AC7(GXBR4K_RX_CH0P,_GXBR4K_REFCLK0P) U1.AC8(GXBR4K_RX_CH0N,_GXBR4K_REFCLK0N) U1.AD5(GXBR4K_RX_CH1P,_GXBR4K_REFCLK1P) U1.AD6(GXBR4K_RX_CH1N,_GXBR4K_REFCLK1N) U1.AD9(REFCLK_GXBR4L_CHBP) U1.AD10(REFCLK_GXBR4L_CHBN) U1.AD40(REFCLK_GXBL1L_CHBN) U1.AD41(REFCLK_GXBL1L_CHBP) U1.AE7(GXBR4F_RX_CH5P,_GXBR4F_REFCLK5P) U1.AE8(GXBR4F_RX_CH5N,_GXBR4F_REFCLK5N) U1.AE42(GXBL1F_RX_CH5N,_GXBL1F_REFCLK5N) U1.AE43(GXBL1F_RX_CH5P,_GXBL1F_REFCLK5P) U1.AF5(GXBR4F_RX_CH3P,_GXBR4F_REFCLK3P) U1.AF6(GXBR4F_RX_CH3N,_GXBR4F_REFCLK3N) U1.AF40(REFCLK_GXBL1E_CHTN) U1.AF41(REFCLK_GXBL1E_CHTP) U1.AF44(GXBL1F_RX_CH3N,_GXBL1F_REFCLK3N) U1.AF45(GXBL1F_RX_CH3P,_GXBL1F_REFCLK3P) U1.AG7(GXBR4F_RX_CH4P,_GXBR4F_REFCLK4P) U1.AG8(GXBR4F_RX_CH4N,_GXBR4F_REFCLK4N) U1.AG42(GXBL1F_RX_CH4N,_GXBL1F_REFCLK4N) U1.AG43(GXBL1F_RX_CH4P,_GXBL1F_REFCLK4P) U1.AH5(GXBR4F_RX_CH1P,_GXBR4F_REFCLK1P) U1.AH6(GXBR4F_RX_CH1N,_GXBR4F_REFCLK1N) U1.AH9(REFCLK_GXBR4E_CHBP) U1.AH10(REFCLK_GXBR4E_CHBN) U1.AH40(REFCLK_GXBL1E_CHBN) U1.AH41(REFCLK_GXBL1E_CHBP) U1.AH44(GXBL1F_RX_CH1N,_GXBL1F_REFCLK1N) U1.AH45(GXBL1F_RX_CH1P,_GXBL1F_REFCLK1P) U1.AJ7(GXBR4F_RX_CH2P,_GXBR4F_REFCLK2P) U1.AJ8(GXBR4F_RX_CH2N,_GXBR4F_REFCLK2N) U1.AJ42(GXBL1F_RX_CH2N,_GXBL1F_REFCLK2N) U1.AJ43(GXBL1F_RX_CH2P,_GXBL1F_REFCLK2P) U1.AK5(GXBR4E_RX_CH5P,_GXBR4E_REFCLK5P) U1.AK6(GXBR4E_RX_CH5N,_GXBR4E_REFCLK5N) U1.AK9(REFCLK_GXBR4D_CHTP) U1.AK10(REFCLK_GXBR4D_CHTN) U1.AK12(REFCLK_GXBR4F_CHTP) U1.AK13(REFCLK_GXBR4F_CHTN) U1.AK44(GXBL1E_RX_CH5N,_GXBL1E_REFCLK5N) U1.AK45(GXBL1E_RX_CH5P,_GXBL1E_REFCLK5P) U1.AL7(GXBR4F_RX_CH0P,_GXBR4F_REFCLK0P) U1.AL8(GXBR4F_RX_CH0N,_GXBR4F_REFCLK0N) U1.AL42(GXBL1F_RX_CH0N,_GXBL1F_REFCLK0N) U1.AL43(GXBL1F_RX_CH0P,_GXBL1F_REFCLK0P) U1.AM5(GXBR4E_RX_CH4P,_GXBR4E_REFCLK4P) U1.AM6(GXBR4E_RX_CH4N,_GXBR4E_REFCLK4N) U1.AM12(REFCLK_GXBR4F_CHBP) U1.AM13(REFCLK_GXBR4F_CHBN) U1.AM37(REFCLK_GXBL1F_CHBN) U1.AM38(REFCLK_GXBL1F_CHBP) U1.AM44(GXBL1E_RX_CH4N,_GXBL1E_REFCLK4N) U1.AM45(GXBL1E_RX_CH4P,_GXBL1E_REFCLK4P) U1.AN32(VREFB2CN0) U1.AR29(VREFB2FN0) U1.AT31(VREFB2BN0) U1.AT40(REFCLK_GXBL1C_CHBN) U1.AT41(REFCLK_GXBL1C_CHBP) U1.AU19(VREFB3AN0) U1.AV31(VREFB2AN0) U1.B9(GXBR4N_RX_CH5P,_GXBR4N_REFCLK5P) U1.B10(GXBR4N_RX_CH5N,_GXBR4N_REFCLK5N) U1.B40(GXBL1N_RX_CH5N,_GXBL1N_REFCLK5N) U1.B41(GXBL1N_RX_CH5P,_GXBL1N_REFCLK5P) U1.C7(GXBR4N_RX_CH3P,_GXBR4N_REFCLK3P) U1.C8(GXBR4N_RX_CH3N,_GXBR4N_REFCLK3N) U1.C42(GXBL1N_RX_CH3N,_GXBL1N_REFCLK3N) U1.C43(GXBL1N_RX_CH3P,_GXBL1N_REFCLK3P) U1.D5(GXBR4N_RX_CH1P,_GXBR4N_REFCLK1P) U1.D6(GXBR4N_RX_CH1N,_GXBR4N_REFCLK1N) U1.D44(GXBL1N_RX_CH1N,_GXBL1N_REFCLK1N) U1.D45(GXBL1N_RX_CH1P,_GXBL1N_REFCLK1P) U1.E7(GXBR4N_RX_CH2P,_GXBR4N_REFCLK2P) U1.E8(GXBR4N_RX_CH2N,_GXBR4N_REFCLK2N) U1.E42(GXBL1N_RX_CH2N,_GXBL1N_REFCLK2N) U1.E43(GXBL1N_RX_CH2P,_GXBL1N_REFCLK2P) U1.F5(GXBR4M_RX_CH5P,_GXBR4M_REFCLK5P) U1.F6(GXBR4M_RX_CH5N,_GXBR4M_REFCLK5N) U1.F44(GXBL1M_RX_CH5N,_GXBL1M_REFCLK5N) U1.F45(GXBL1M_RX_CH5P,_GXBL1M_REFCLK5P) U1.G7(GXBR4N_RX_CH0P,_GXBR4N_REFCLK0P) U1.G8(GXBR4N_RX_CH0N,_GXBR4N_REFCLK0N) U1.H5(GXBR4M_RX_CH3P,_GXBR4M_REFCLK3P) U1.H6(GXBR4M_RX_CH3N,_GXBR4M_REFCLK3N) U1.H44(GXBL1M_RX_CH3N,_GXBL1M_REFCLK3N) U1.H45(GXBL1M_RX_CH3P,_GXBL1M_REFCLK3P) U1.J7(GXBR4M_RX_CH4P,_GXBR4M_REFCLK4P) U1.J8(GXBR4M_RX_CH4N,_GXBR4M_REFCLK4N) U1.J42(GXBL1M_RX_CH4N,_GXBL1M_REFCLK4N) U1.J43(GXBL1M_RX_CH4P,_GXBL1M_REFCLK4P) U1.K5(GXBR4M_RX_CH1P,_GXBR4M_REFCLK1P) U1.K6(GXBR4M_RX_CH1N,_GXBR4M_REFCLK1N) U1.K44(GXBL1M_RX_CH1N,_GXBL1M_REFCLK1N) U1.K45(GXBL1M_RX_CH1P,_GXBL1M_REFCLK1P) U1.L7(GXBR4M_RX_CH2P,_GXBR4M_REFCLK2P) U1.L8(GXBR4M_RX_CH2N,_GXBR4M_REFCLK2N) U1.L42(GXBL1M_RX_CH2N,_GXBL1M_REFCLK2N) U1.L43(GXBL1M_RX_CH2P,_GXBL1M_REFCLK2P) U1.M5(GXBR4L_RX_CH5P,_GXBR4L_REFCLK5P) U1.M6(GXBR4L_RX_CH5N,_GXBR4L_REFCLK5N) U1.M19(VREFB3LN0) U1.M44(GXBL1L_RX_CH5N,_GXBL1L_REFCLK5N) U1.M45(GXBL1L_RX_CH5P,_GXBL1L_REFCLK5P) U1.N7(GXBR4M_RX_CH0P,_GXBR4M_REFCLK0P) U1.N8(GXBR4M_RX_CH0N,_GXBR4M_REFCLK0N) U1.N42(GXBL1M_RX_CH0N,_GXBL1M_REFCLK0N) U1.N43(GXBL1M_RX_CH0P,_GXBL1M_REFCLK0P) U1.P5(GXBR4L_RX_CH3P,_GXBR4L_REFCLK3P) U1.P6(GXBR4L_RX_CH3N,_GXBR4L_REFCLK3N) U1.P9(REFCLK_GXBR4N_CHTP) U1.P10(REFCLK_GXBR4N_CHTN) U1.P19(VREFB3KN0) U1.P44(GXBL1L_RX_CH3N,_GXBL1L_REFCLK3N) U1.P45(GXBL1L_RX_CH3P,_GXBL1L_REFCLK3P) U1.R7(GXBR4L_RX_CH4P,_GXBR4L_REFCLK4P) U1.R8(GXBR4L_RX_CH4N,_GXBR4L_REFCLK4N) U1.R42(GXBL1L_RX_CH4N,_GXBL1L_REFCLK4N) U1.R43(GXBL1L_RX_CH4P,_GXBL1L_REFCLK4P) U1.T5(GXBR4L_RX_CH2P,_GXBR4L_REFCLK2P) U1.T6(GXBR4L_RX_CH2N,_GXBR4L_REFCLK2N) U1.T9(REFCLK_GXBR4N_CHBP) U1.T10(REFCLK_GXBR4N_CHBN) U1.T44(GXBL1L_RX_CH2N,_GXBL1L_REFCLK2N) U1.T45(GXBL1L_RX_CH2P,_GXBL1L_REFCLK2P) U1.U7(GXBR4L_RX_CH1P,_GXBR4L_REFCLK1P) U1.U8(GXBR4L_RX_CH1N,_GXBR4L_REFCLK1N) U1.U16(VREFB3JN0) U1.U42(GXBL1L_RX_CH1N,_GXBL1L_REFCLK1N) U1.U43(GXBL1L_RX_CH1P,_GXBL1L_REFCLK1P) U1.V5(GXBR4L_RX_CH0P,_GXBR4L_REFCLK0P) U1.V6(GXBR4L_RX_CH0N,_GXBR4L_REFCLK0N) U1.V9(REFCLK_GXBR4M_CHTP) U1.V10(REFCLK_GXBR4M_CHTN) U1.V12(REFCLK_GXBR4K_CHTP) U1.V13(REFCLK_GXBR4K_CHTN) U1.V20(VREFB3IN0) U1.V37(REFCLK_GXBL1K_CHTN) U1.V38(REFCLK_GXBL1K_CHTP) U1.V40(REFCLK_GXBL1M_CHTN) U1.V41(REFCLK_GXBL1M_CHTP) U1.V44(GXBL1L_RX_CH0N,_GXBL1L_REFCLK0N) U1.V45(GXBL1L_RX_CH0P,_GXBL1L_REFCLK0P) U1.W7(GXBR4K_RX_CH4P,_GXBR4K_REFCLK4P) U1.W8(GXBR4K_RX_CH4N,_GXBR4K_REFCLK4N) U1.Y5(GXBR4K_RX_CH5P,_GXBR4K_REFCLK5P) U1.Y6(GXBR4K_RX_CH5N,_GXBR4K_REFCLK5N) U1.Y9(REFCLK_GXBR4M_CHBP) U1.Y10(REFCLK_GXBR4M_CHBN) U1.Y12(REFCLK_GXBR4K_CHBP) U1.Y13(REFCLK_GXBR4K_CHBN) U1.Y40(REFCLK_GXBL1M_CHBN) U1.Y41(REFCLK_GXBL1M_CHBP) U1.Y44(GXBL1K_RX_CH5N,_GXBL1K_REFCLK5N) U1.Y45(GXBL1K_RX_CH5P,_GXBL1K_REFCLK5P) ; also on sheet 6 7 8 9 16 17 18 19 20 21 23 24 25 27 28 29 30 31 32 33 34 35 36 37 38 39 40 41 42 43 44 45 46
VCCIO3V: U1.AF14(VCCIO3V) U1.AF36(VCCIO3V) U1.AG14(VCCIO3V) U1.AG36(VCCIO3V) ; also on sheet 6 31 44 45 46
VCCPFUSE_SDM: C533.1 U1.AV23(VCCFUSEWR_SDM) ; also on sheet 31 43 46
CLK_FPGA_B3L_N: R5299.1 U1.J19(IO,_CLK_3L_0N,_LVDS3L_13N,_DQ50) ; also on sheet 18
CLK_FPGA_B3L_P: R5299.2 U1.J20(IO,_CLK_3L_0P,_LVDS3L_13P,_DQ50) ; also on sheet 18
CPU_RESETn: U1.A20(IO,_LVDS3L_3P,_DQ48) ; also on sheet 19 29
DP_ML_LANE_N0: U1.AK48(GXBL1F_TX_CH0N) ; also on sheet 24
DP_ML_LANE_N1: U1.AL46(GXBL1F_TX_CH1N) ; also on sheet 24
DP_ML_LANE_N2: U1.AH48(GXBL1F_TX_CH2N) ; also on sheet 24
DP_ML_LANE_N3: U1.AJ46(GXBL1F_TX_CH3N) ; also on sheet 24
DP_ML_LANE_P0: U1.AK49(GXBL1F_TX_CH0P) ; also on sheet 24
DP_ML_LANE_P1: U1.AL47(GXBL1F_TX_CH1P) ; also on sheet 24
DP_ML_LANE_P2: U1.AH49(GXBL1F_TX_CH2P) ; also on sheet 24
DP_ML_LANE_P3: U1.AJ47(GXBL1F_TX_CH3P) ; also on sheet 24
FMCA_DP_C2M_N0: U1.BJ5(GXBR4C_TX_CH0N) ; also on sheet 25
FMCA_DP_C2M_N1: U1.BF6(GXBR4C_TX_CH1N) ; also on sheet 25
FMCA_DP_C2M_N2: U1.BG4(GXBR4C_TX_CH2N) ; also on sheet 25
FMCA_DP_C2M_N3: U1.BE4(GXBR4C_TX_CH3N) ; also on sheet 25
FMCA_DP_C2M_N4: U1.BF2(GXBR4C_TX_CH4N) ; also on sheet 25
FMCA_DP_C2M_N5: U1.BC4(GXBR4C_TX_CH5N) ; also on sheet 25
FMCA_DP_C2M_N6: U1.BD2(GXBR4D_TX_CH0N) ; also on sheet 25
FMCA_DP_C2M_N7: U1.BA4(GXBR4D_TX_CH1N) ; also on sheet 25
FMCA_DP_C2M_N8: U1.BB2(GXBR4D_TX_CH2N) ; also on sheet 25
FMCA_DP_C2M_N9: U1.AW4(GXBR4D_TX_CH3N) ; also on sheet 25
FMCA_DP_C2M_N10: U1.AY2(GXBR4D_TX_CH4N) ; also on sheet 25
FMCA_DP_C2M_N11: U1.AU4(GXBR4D_TX_CH5N) ; also on sheet 25
FMCA_DP_C2M_N12: U1.AV2(GXBR4E_TX_CH0N) ; also on sheet 25
FMCA_DP_C2M_N13: U1.AR4(GXBR4E_TX_CH1N) ; also on sheet 25
FMCA_DP_C2M_N14: U1.AT2(GXBR4E_TX_CH2N) ; also on sheet 25
FMCA_DP_C2M_N15: U1.AP2(GXBR4E_TX_CH3N) ; also on sheet 25
FMCA_DP_C2M_P0: U1.BJ4(GXBR4C_TX_CH0P) ; also on sheet 25
FMCA_DP_C2M_P1: U1.BF5(GXBR4C_TX_CH1P) ; also on sheet 25
FMCA_DP_C2M_P2: U1.BG3(GXBR4C_TX_CH2P) ; also on sheet 25
FMCA_DP_C2M_P3: U1.BE3(GXBR4C_TX_CH3P) ; also on sheet 25
FMCA_DP_C2M_P4: U1.BF1(GXBR4C_TX_CH4P) ; also on sheet 25
FMCA_DP_C2M_P5: U1.BC3(GXBR4C_TX_CH5P) ; also on sheet 25
FMCA_DP_C2M_P6: U1.BD1(GXBR4D_TX_CH0P) ; also on sheet 25
FMCA_DP_C2M_P7: U1.BA3(GXBR4D_TX_CH1P) ; also on sheet 25
FMCA_DP_C2M_P8: U1.BB1(GXBR4D_TX_CH2P) ; also on sheet 25
FMCA_DP_C2M_P9: U1.AW3(GXBR4D_TX_CH3P) ; also on sheet 25
FMCA_DP_C2M_P10: U1.AY1(GXBR4D_TX_CH4P) ; also on sheet 25
FMCA_DP_C2M_P11: U1.AU3(GXBR4D_TX_CH5P) ; also on sheet 25
FMCA_DP_C2M_P12: U1.AV1(GXBR4E_TX_CH0P) ; also on sheet 25
FMCA_DP_C2M_P13: U1.AR3(GXBR4E_TX_CH1P) ; also on sheet 25
FMCA_DP_C2M_P14: U1.AT1(GXBR4E_TX_CH2P) ; also on sheet 25
FMCA_DP_C2M_P15: U1.AP1(GXBR4E_TX_CH3P) ; also on sheet 25
FMCA_DP_M2C_N0: U1.BH10(GXBR4C_RX_CH0N,_GXBR4C_REFCLK0N) ; also on sheet 25
FMCA_DP_M2C_N1: U1.BJ8(GXBR4C_RX_CH1N,_GXBR4C_REFCLK1N) ; also on sheet 25
FMCA_DP_M2C_N2: U1.BG8(GXBR4C_RX_CH2N,_GXBR4C_REFCLK2N) ; also on sheet 25
FMCA_DP_M2C_N3: U1.BE8(GXBR4C_RX_CH3N,_GXBR4C_REFCLK3N) ; also on sheet 25
FMCA_DP_M2C_N4: U1.BC8(GXBR4C_RX_CH4N,_GXBR4C_REFCLK4N) ; also on sheet 25
FMCA_DP_M2C_N5: U1.BD6(GXBR4C_RX_CH5N,_GXBR4C_REFCLK5N) ; also on sheet 25
FMCA_DP_M2C_N6: U1.BA8(GXBR4D_RX_CH0N,_GXBR4D_REFCLK0N) ; also on sheet 25
FMCA_DP_M2C_N7: U1.BB6(GXBR4D_RX_CH1N,_GXBR4D_REFCLK1N) ; also on sheet 25
FMCA_DP_M2C_N8: U1.AW8(GXBR4D_RX_CH2N,_GXBR4D_REFCLK2N) ; also on sheet 25
FMCA_DP_M2C_N9: U1.AY6(GXBR4D_RX_CH3N,_GXBR4D_REFCLK3N) ; also on sheet 25
FMCA_DP_M2C_N10: U1.AU8(GXBR4D_RX_CH4N,_GXBR4D_REFCLK4N) ; also on sheet 25
FMCA_DP_M2C_N11: U1.AV6(GXBR4D_RX_CH5N,_GXBR4D_REFCLK5N) ; also on sheet 25
FMCA_DP_M2C_N12: U1.AR8(GXBR4E_RX_CH0N,_GXBR4E_REFCLK0N) ; also on sheet 25
FMCA_DP_M2C_N13: U1.AT6(GXBR4E_RX_CH1N,_GXBR4E_REFCLK1N) ; also on sheet 25
FMCA_DP_M2C_N14: U1.AP6(GXBR4E_RX_CH2N,_GXBR4E_REFCLK2N) ; also on sheet 25
FMCA_DP_M2C_N15: U1.AN8(GXBR4E_RX_CH3N,_GXBR4E_REFCLK3N) ; also on sheet 25
FMCA_DP_M2C_P0: U1.BH9(GXBR4C_RX_CH0P,_GXBR4C_REFCLK0P) ; also on sheet 25
FMCA_DP_M2C_P1: U1.BJ7(GXBR4C_RX_CH1P,_GXBR4C_REFCLK1P) ; also on sheet 25
FMCA_DP_M2C_P2: U1.BG7(GXBR4C_RX_CH2P,_GXBR4C_REFCLK2P) ; also on sheet 25
FMCA_DP_M2C_P3: U1.BE7(GXBR4C_RX_CH3P,_GXBR4C_REFCLK3P) ; also on sheet 25
FMCA_DP_M2C_P4: U1.BC7(GXBR4C_RX_CH4P,_GXBR4C_REFCLK4P) ; also on sheet 25
FMCA_DP_M2C_P5: U1.BD5(GXBR4C_RX_CH5P,_GXBR4C_REFCLK5P) ; also on sheet 25
FMCA_DP_M2C_P6: U1.BA7(GXBR4D_RX_CH0P,_GXBR4D_REFCLK0P) ; also on sheet 25
FMCA_DP_M2C_P7: U1.BB5(GXBR4D_RX_CH1P,_GXBR4D_REFCLK1P) ; also on sheet 25
FMCA_DP_M2C_P8: U1.AW7(GXBR4D_RX_CH2P,_GXBR4D_REFCLK2P) ; also on sheet 25
FMCA_DP_M2C_P9: U1.AY5(GXBR4D_RX_CH3P,_GXBR4D_REFCLK3P) ; also on sheet 25
FMCA_DP_M2C_P10: U1.AU7(GXBR4D_RX_CH4P,_GXBR4D_REFCLK4P) ; also on sheet 25
FMCA_DP_M2C_P11: U1.AV5(GXBR4D_RX_CH5P,_GXBR4D_REFCLK5P) ; also on sheet 25
FMCA_DP_M2C_P12: U1.AR7(GXBR4E_RX_CH0P,_GXBR4E_REFCLK0P) ; also on sheet 25
FMCA_DP_M2C_P13: U1.AT5(GXBR4E_RX_CH1P,_GXBR4E_REFCLK1P) ; also on sheet 25
FMCA_DP_M2C_P14: U1.AP5(GXBR4E_RX_CH2P,_GXBR4E_REFCLK2P) ; also on sheet 25
FMCA_DP_M2C_P15: U1.AN7(GXBR4E_RX_CH3P,_GXBR4E_REFCLK3P) ; also on sheet 25
FMCA_GBTCLK_M2C_N0: U1.AP10(REFCLK_GXBR4C_CHTN) ; also on sheet 25
FMCA_GBTCLK_M2C_N1: U1.AM10(REFCLK_GXBR4D_CHBN) ; also on sheet 25
FMCA_GBTCLK_M2C_P0: U1.AP9(REFCLK_GXBR4C_CHTP) ; also on sheet 25
FMCA_GBTCLK_M2C_P1: U1.AM9(REFCLK_GXBR4D_CHBP) ; also on sheet 25
FMCA_PRSNTn: U1.B22(IO,_LVDS3L_5N,_DQ48) ; also on sheet 19 25 29 30
FMCA_RX_LED: U1.A17(IO,_LVDS3L_2P,_DQ48) ; also on sheet 29
FMCA_TX_LED: U1.A21(IO,_LVDS3L_3N,_DQ48) ; also on sheet 29
HILO_VREF: U1.M32(VREFB2NN0) U1.P31(VREFB2MN0) U1.V31(VREFB2LN0) ; also on sheet 23 45
LT_IO_SCL: U1.V21(IO,_LVDS3I_1N,_DQ60) ; also on sheet 6
LT_IO_SDA: U1.V22(IO,_LVDS3I_1P,_DQ60) ; also on sheet 6
OVERTEMPn_1.8V: U1.R21(IO,_LVDS3I_2P,_DQ60) ; also on sheet 19
PCIE_EDGE_REFCLK_N: U1.AK40(REFCLK_GXBL1D_CHTN) ; also on sheet 17
PCIE_EDGE_REFCLK_P: U1.AK41(REFCLK_GXBL1D_CHTP) ; also on sheet 17
PCIE_LED_G2: U1.N20(IO,_LVDS3L_24N,_DQ51) ; also on sheet 29
PCIE_LED_G3: U1.P20(IO,_LVDS3L_24P,_DQ51) ; also on sheet 29
PCIE_LED_X1: U1.L21(IO,_LVDS3L_21N,_DQ51) ; also on sheet 29
PCIE_LED_X4: U1.K21(IO,_LVDS3L_21P,_DQ51) ; also on sheet 29
PCIE_LED_X8: U1.N21(IO,_LVDS3L_23N,_DQ51) ; also on sheet 29
PCIE_LED_X16: U1.P21(IO,_LVDS3L_23P,_DQ51) ; also on sheet 29
PCIE_OB_REFCLK_N: U1.AP40(REFCLK_GXBL1C_CHTN) ; also on sheet 18
PCIE_OB_REFCLK_P: U1.AP41(REFCLK_GXBL1C_CHTP) ; also on sheet 18
PCIE_RX_N0: U1.BH40(GXBL1C_RX_CH0N,_GXBL1C_REFCLK0N) ; also on sheet 17
PCIE_RX_N1: U1.BJ42(GXBL1C_RX_CH1N,_GXBL1C_REFCLK1N) ; also on sheet 17
PCIE_RX_N2: U1.BG42(GXBL1C_RX_CH2N,_GXBL1C_REFCLK2N) ; also on sheet 17
PCIE_RX_N3: U1.BE42(GXBL1C_RX_CH3N,_GXBL1C_REFCLK3N) ; also on sheet 17
PCIE_RX_N4: U1.BC42(GXBL1C_RX_CH4N,_GXBL1C_REFCLK4N) ; also on sheet 17
PCIE_RX_N5: U1.BD44(GXBL1C_RX_CH5N,_GXBL1C_REFCLK5N) ; also on sheet 17
PCIE_RX_N6: U1.BA42(GXBL1D_RX_CH0N,_GXBL1D_REFCLK0N) ; also on sheet 17
PCIE_RX_N7: U1.BB44(GXBL1D_RX_CH1N,_GXBL1D_REFCLK1N) ; also on sheet 17
PCIE_RX_N8: U1.AW42(GXBL1D_RX_CH2N,_GXBL1D_REFCLK2N) ; also on sheet 17
PCIE_RX_N9: U1.AY44(GXBL1D_RX_CH3N,_GXBL1D_REFCLK3N) ; also on sheet 17
PCIE_RX_N10: U1.AU42(GXBL1D_RX_CH4N,_GXBL1D_REFCLK4N) ; also on sheet 17
PCIE_RX_N11: U1.AV44(GXBL1D_RX_CH5N,_GXBL1D_REFCLK5N) ; also on sheet 17
PCIE_RX_N12: U1.AR42(GXBL1E_RX_CH0N,_GXBL1E_REFCLK0N) ; also on sheet 17
PCIE_RX_N13: U1.AT44(GXBL1E_RX_CH1N,_GXBL1E_REFCLK1N) ; also on sheet 17
PCIE_RX_N14: U1.AP44(GXBL1E_RX_CH2N,_GXBL1E_REFCLK2N) ; also on sheet 17
PCIE_RX_N15: U1.AN42(GXBL1E_RX_CH3N,_GXBL1E_REFCLK3N) ; also on sheet 17
PCIE_RX_P0: U1.BH41(GXBL1C_RX_CH0P,_GXBL1C_REFCLK0P) ; also on sheet 17
PCIE_RX_P1: U1.BJ43(GXBL1C_RX_CH1P,_GXBL1C_REFCLK1P) ; also on sheet 17
PCIE_RX_P2: U1.BG43(GXBL1C_RX_CH2P,_GXBL1C_REFCLK2P) ; also on sheet 17
PCIE_RX_P3: U1.BE43(GXBL1C_RX_CH3P,_GXBL1C_REFCLK3P) ; also on sheet 17
PCIE_RX_P4: U1.BC43(GXBL1C_RX_CH4P,_GXBL1C_REFCLK4P) ; also on sheet 17
PCIE_RX_P5: U1.BD45(GXBL1C_RX_CH5P,_GXBL1C_REFCLK5P) ; also on sheet 17
PCIE_RX_P6: U1.BA43(GXBL1D_RX_CH0P,_GXBL1D_REFCLK0P) ; also on sheet 17
PCIE_RX_P7: U1.BB45(GXBL1D_RX_CH1P,_GXBL1D_REFCLK1P) ; also on sheet 17
PCIE_RX_P8: U1.AW43(GXBL1D_RX_CH2P,_GXBL1D_REFCLK2P) ; also on sheet 17
PCIE_RX_P9: U1.AY45(GXBL1D_RX_CH3P,_GXBL1D_REFCLK3P) ; also on sheet 17
PCIE_RX_P10: U1.AU43(GXBL1D_RX_CH4P,_GXBL1D_REFCLK4P) ; also on sheet 17
PCIE_RX_P11: U1.AV45(GXBL1D_RX_CH5P,_GXBL1D_REFCLK5P) ; also on sheet 17
PCIE_RX_P12: U1.AR43(GXBL1E_RX_CH0P,_GXBL1E_REFCLK0P) ; also on sheet 17
PCIE_RX_P13: U1.AT45(GXBL1E_RX_CH1P,_GXBL1E_REFCLK1P) ; also on sheet 17
PCIE_RX_P14: U1.AP45(GXBL1E_RX_CH2P,_GXBL1E_REFCLK2P) ; also on sheet 17
PCIE_RX_P15: U1.AN43(GXBL1E_RX_CH3P,_GXBL1E_REFCLK3P) ; also on sheet 17
PCIE_TX_N0: U1.BJ45(GXBL1C_TX_CH0N) ; also on sheet 17
PCIE_TX_N1: U1.BF44(GXBL1C_TX_CH1N) ; also on sheet 17
PCIE_TX_N2: U1.BG46(GXBL1C_TX_CH2N) ; also on sheet 17
PCIE_TX_N3: U1.BE46(GXBL1C_TX_CH3N) ; also on sheet 17
PCIE_TX_N4: U1.BF48(GXBL1C_TX_CH4N) ; also on sheet 17
PCIE_TX_N5: U1.BC46(GXBL1C_TX_CH5N) ; also on sheet 17
PCIE_TX_N6: U1.BD48(GXBL1D_TX_CH0N) ; also on sheet 17
PCIE_TX_N7: U1.BA46(GXBL1D_TX_CH1N) ; also on sheet 17
PCIE_TX_N8: U1.BB48(GXBL1D_TX_CH2N) ; also on sheet 17
PCIE_TX_N9: U1.AW46(GXBL1D_TX_CH3N) ; also on sheet 17
PCIE_TX_N10: U1.AY48(GXBL1D_TX_CH4N) ; also on sheet 17
PCIE_TX_N11: U1.AU46(GXBL1D_TX_CH5N) ; also on sheet 17
PCIE_TX_N12: U1.AV48(GXBL1E_TX_CH0N) ; also on sheet 17
PCIE_TX_N13: U1.AR46(GXBL1E_TX_CH1N) ; also on sheet 17
PCIE_TX_N14: U1.AT48(GXBL1E_TX_CH2N) ; also on sheet 17
PCIE_TX_N15: U1.AP48(GXBL1E_TX_CH3N) ; also on sheet 17
PCIE_TX_P0: U1.BJ46(GXBL1C_TX_CH0P) ; also on sheet 17
PCIE_TX_P1: U1.BF45(GXBL1C_TX_CH1P) ; also on sheet 17
PCIE_TX_P2: U1.BG47(GXBL1C_TX_CH2P) ; also on sheet 17
PCIE_TX_P3: U1.BE47(GXBL1C_TX_CH3P) ; also on sheet 17
PCIE_TX_P4: U1.BF49(GXBL1C_TX_CH4P) ; also on sheet 17
PCIE_TX_P5: U1.BC47(GXBL1C_TX_CH5P) ; also on sheet 17
PCIE_TX_P6: U1.BD49(GXBL1D_TX_CH0P) ; also on sheet 17
PCIE_TX_P7: U1.BA47(GXBL1D_TX_CH1P) ; also on sheet 17
PCIE_TX_P8: U1.BB49(GXBL1D_TX_CH2P) ; also on sheet 17
PCIE_TX_P9: U1.AW47(GXBL1D_TX_CH3P) ; also on sheet 17
PCIE_TX_P10: U1.AY49(GXBL1D_TX_CH4P) ; also on sheet 17
PCIE_TX_P11: U1.AU47(GXBL1D_TX_CH5P) ; also on sheet 17
PCIE_TX_P12: U1.AV49(GXBL1E_TX_CH0P) ; also on sheet 17
PCIE_TX_P13: U1.AR47(GXBL1E_TX_CH1P) ; also on sheet 17
PCIE_TX_P14: U1.AT49(GXBL1E_TX_CH2P) ; also on sheet 17
PCIE_TX_P15: U1.AP49(GXBL1E_TX_CH3P) ; also on sheet 17
QSFP1_RX_N0: U1.AC42(GXBL1K_RX_CH0N,_GXBL1K_REFCLK0N) ; also on sheet 27
QSFP1_RX_N1: U1.W42(GXBL1K_RX_CH4N,_GXBL1K_REFCLK4N) ; also on sheet 27
QSFP1_RX_N2: U1.AB44(GXBL1K_RX_CH3N,_GXBL1K_REFCLK3N) ; also on sheet 27
QSFP1_RX_N3: U1.AD44(GXBL1K_RX_CH1N,_GXBL1K_REFCLK1N) ; also on sheet 27
QSFP1_RX_P0: U1.AC43(GXBL1K_RX_CH0P,_GXBL1K_REFCLK0P) ; also on sheet 27
QSFP1_RX_P1: U1.W43(GXBL1K_RX_CH4P,_GXBL1K_REFCLK4P) ; also on sheet 27
QSFP1_RX_P2: U1.AB45(GXBL1K_RX_CH3P,_GXBL1K_REFCLK3P) ; also on sheet 27
QSFP1_RX_P3: U1.AD45(GXBL1K_RX_CH1P,_GXBL1K_REFCLK1P) ; also on sheet 27
QSFP1_TX_N0: U1.AE46(GXBL1K_TX_CH0N) ; also on sheet 27
QSFP1_TX_N1: U1.AB48(GXBL1K_TX_CH4N) ; also on sheet 27
QSFP1_TX_N2: U1.AA46(GXBL1K_TX_CH3N) ; also on sheet 27
QSFP1_TX_N3: U1.AC46(GXBL1K_TX_CH1N) ; also on sheet 27
QSFP1_TX_P0: U1.AE47(GXBL1K_TX_CH0P) ; also on sheet 27
QSFP1_TX_P1: U1.AB49(GXBL1K_TX_CH4P) ; also on sheet 27
QSFP1_TX_P2: U1.AA47(GXBL1K_TX_CH3P) ; also on sheet 27
QSFP1_TX_P3: U1.AC47(GXBL1K_TX_CH1P) ; also on sheet 27
REFCLK1_N: U1.AM40(REFCLK_GXBL1D_CHBN) ; also on sheet 18
REFCLK1_P: U1.AM41(REFCLK_GXBL1D_CHBP) ; also on sheet 18
REFCLK4_N: U1.AF10(REFCLK_GXBR4E_CHTN) ; also on sheet 18
REFCLK4_P: U1.AF9(REFCLK_GXBR4E_CHTP) ; also on sheet 18
REFCLK_DP_N: U1.AK37(REFCLK_GXBL1F_CHTN) ; also on sheet 18
REFCLK_DP_P: U1.AK38(REFCLK_GXBL1F_CHTP) ; also on sheet 18
REFCLK_FMCA_N: U1.AT10(REFCLK_GXBR4C_CHBN) ; also on sheet 18
REFCLK_FMCA_P: U1.AT9(REFCLK_GXBR4C_CHBP) ; also on sheet 18
REFCLK_QSFP1_N: U1.Y37(REFCLK_GXBL1K_CHBN) ; also on sheet 18
REFCLK_QSFP1_P: U1.Y38(REFCLK_GXBL1K_CHBP) ; also on sheet 18
REFCLK_SDI_N: U1.P40(REFCLK_GXBL1N_CHTN) ; also on sheet 18
REFCLK_SDI_P: U1.P41(REFCLK_GXBL1N_CHTP) ; also on sheet 18
S10_SI516_FS: R37.2 ; also on sheet 28
S10_VCC: R5364.2 U1.AA15(VCC) U1.AA16(VCC) U1.AA17(VCC) U1.AA19(VCC) U1.AA20(VCC) U1.AA21(VCC) U1.AA22(VCC) U1.AA24(VCC) U1.AA25(VCC) U1.AA26(VCC) U1.AA27(VCC) U1.AA29(VCC) U1.AA30(VCC) U1.AA31(VCC) U1.AA32(VCC) U1.AA34(VCC) U1.AA35(VCC) U1.AB17(VCC) U1.AB18(VCC) U1.AB19(VCC) U1.AB20(VCC) U1.AB22(VCC) U1.AB23(VCC) U1.AB24(VCC) U1.AB25(VCC) U1.AB27(VCC) U1.AB28(VCC) U1.AB29(VCC) U1.AB30(VCC) U1.AB32(VCC) U1.AB33(VCC) U1.AC16(VCC) U1.AC17(VCC) U1.AC18(VCC) U1.AC20(VCC) U1.AC21(VCC) U1.AC22(VCC) U1.AC23(VCC) U1.AC25(VCC) U1.AC26(VCC) U1.AC27(VCC) U1.AC28(VCC) U1.AC30(VCC) U1.AC31(VCC) U1.AC32(VCC) U1.AD18(VCC) U1.AD19(VCC) U1.AD20(VCC) U1.AD21(VCC) U1.AD23(VCC) U1.AD24(VCC) U1.AD25(VCC) U1.AD26(VCC) U1.AD28(VCC) U1.AD29(VCC) U1.AD30(VCC) U1.AD31(VCC) U1.AD33(VCC) U1.AE19(VCC) U1.AE23(VCC) U1.AE27(VCC) U1.AE31(VCC) U1.AE34(VCC) U1.AF19(VCC) U1.AF20(VCC) U1.AF21(VCC) U1.AF22(VCC) U1.AF27(VCC) U1.AF29(VCC) U1.AF30(VCC) U1.AF31(VCC) U1.AF32(VCC) U1.AF35(VCC) U1.AG15(VCC) U1.AG19(VCC) U1.AG23(VCC) U1.AG28(VCC) U1.AH15(VCC) U1.AH18(VCC) U1.AH20(VCC) U1.AH21(VCC) U1.AH22(VCC) U1.AH23(VCC) U1.AH25(VCC) U1.AH26(VCC) U1.AH27(VCC) U1.AH28(VCC) U1.AH30(VCC) U1.AH31(VCC) U1.AJ15(VCC) U1.AJ16(VCC) U1.AJ18(VCC) U1.AJ19(VCC) U1.AJ20(VCC) U1.AJ21(VCC) U1.AJ23(VCC) U1.AJ24(VCC) U1.AJ25(VCC) U1.AJ26(VCC) U1.AJ28(VCC) U1.AJ29(VCC) U1.AJ30(VCC) U1.AJ31(VCC) U1.AJ35(VCC) U1.AK16(VCC) U1.AK17(VCC) U1.AK18(VCC) U1.AK19(VCC) U1.AK21(VCC) U1.AK22(VCC) U1.AK23(VCC) U1.AK24(VCC) U1.AK26(VCC) U1.AK27(VCC) U1.AK28(VCC) U1.AK29(VCC) U1.AK31(VCC) U1.AK32(VCC) U1.AK33(VCC) U1.AK34(VCC) U1.AL17(VCC) U1.AL19(VCC) U1.AL20(VCCP) U1.AL21(VCC) U1.AL22(VCC) U1.AL23(VCC) U1.AL24(VCC) U1.AL25(VCC) U1.AL26(VCC) U1.AL27(VCC) U1.AL29(VCC) U1.AL30(VCC) U1.AL32(VCC) U1.AM17(VCC) U1.AM18(VCC) U1.AM19(VCC) U1.AM24(VCC) U1.AM25(VCC) U1.AM26(VCC) U1.AM28(VCC) U1.AM29(VCC) U1.AM30(VCC) U1.AM31(VCC) U1.AM32(VCC) U1.AM33(VCC) U1.AN30(VCCP) U1.L29(VCC) U1.L30(VCC) U1.M28(VCC) U1.M29(VCC) U1.M30(VCC) U1.W19(VCCP) U1.W31(VCCP) U1.Y16(VCC) U1.Y17(VCC) U1.Y18(VCC) U1.Y19(VCC) U1.Y20(VCC) U1.Y21(VCC) U1.Y22(VCC) U1.Y23(VCC) U1.Y24(VCC) U1.Y25(VCC) U1.Y26(VCC) U1.Y27(VCC) U1.Y28(VCC) U1.Y29(VCC) U1.Y30(VCC) U1.Y31(VCC) U1.Y32(VCC) U1.Y33(VCC) U1.Y34(VCC) ; also on sheet 16 31 35 36 37 45
S10_VCC_SENSE: C859.2 R5371.1 ; also on sheet 6 35
S10_VCCH_GXBL: FB1.2 U1.AA39(VCCH_GXBL) U1.AB38(VCCH_GXBL) U1.AF25(VCCA_PLL) U1.AF26(VCCA_PLL) U1.AH38(VCCH_GXBL) U1.AJ36(VCCH_GXBL) U1.AJ39(VCCH_GXBL) U1.AN39(VCCH_GXBL) U1.N39(VCCH_GXBL) U1.U39(VCCH_GXBL) ; also on sheet 16 45
S10_VCCH_GXBR: FB2.2 U1.AA11(VCCH_GXBR) U1.AH12(VCCH_GXBR) U1.AJ11(VCCH_GXBR) U1.AJ14(VCCH_GXBR) U1.AN11(VCCH_GXBR) U1.AU22(VCCPLL_SDM) U1.AY23(VCCADC) U1.N11(VCCH_GXBR) U1.T12(VCCH_GXBR) U1.U11(VCCH_GXBR) ; also on sheet 45
S10_VCCIO_FMCA: U1.AP22(VCCIO3C) U1.AR15(VCCIO3B) U1.AR20(VCCIO3C) U1.AT13(VCCIO3B) U1.AU16(VCCIO3B) U1.AU21(VCCIO3C) ; also on sheet 9 25 31 41 45
S10_VCCIO_HILO: U1.H34(VCCIO2N) U1.J32(VCCIO2N) U1.L33(VCCIO2N) U1.N34(VCCIO2M) U1.R35(VCCIO2M) U1.T28(VCCIO2L) U1.T33(VCCIO2M) U1.U26(VCCIO2L) U1.V29(VCCIO2L) ; also on sheet 31 42 45
S10_VCCPLLDIG_SDM: C532.1 U1.AT22(VCCPLLDIG_SDM) ; also on sheet 38
S10_VCCR_GXB: U1.AC9(VCCR_GXBR4K) U1.AC10(VCCR_GXBR4K) U1.AC11(VCCR_GXBR4K) U1.AC39(VCCR_GXBL1K) U1.AC40(VCCR_GXBL1K) U1.AC41(VCCR_GXBL1K) U1.AG9(VCCR_GXBR4F) U1.AG10(VCCR_GXBR4F) U1.AG11(VCCR_GXBR4F) U1.AG39(VCCR_GXBL1F) U1.AG40(VCCR_GXBL1F) U1.AG41(VCCR_GXBL1F) U1.AL9(VCCR_GXBR4D) U1.AL10(VCCR_GXBR4D) U1.AL11(VCCR_GXBR4D) U1.AL12(VCCR_GXBR4E) U1.AL13(VCCR_GXBR4E) U1.AL14(VCCR_GXBR4E) U1.AL36(VCCR_GXBL1E) U1.AL37(VCCR_GXBL1E) U1.AL38(VCCR_GXBL1E) U1.AL39(VCCR_GXBL1D) U1.AL40(VCCR_GXBL1D) U1.AL41(VCCR_GXBL1D) U1.AR9(VCCR_GXBR4C) U1.AR10(VCCR_GXBR4C) U1.AR11(VCCR_GXBR4C) U1.AR39(VCCR_GXBL1C) U1.AR40(VCCR_GXBL1C) U1.AR41(VCCR_GXBL1C) U1.R9(VCCR_GXBR4N) U1.R10(VCCR_GXBR4N) U1.R11(VCCR_GXBR4N) U1.R39(VCCR_GXBL1N) U1.R40(VCCR_GXBL1N) U1.R41(VCCR_GXBL1N) U1.W9(VCCR_GXBR4M) U1.W10(VCCR_GXBR4M) U1.W11(VCCR_GXBR4M) U1.W12(VCCR_GXBR4L) U1.W13(VCCR_GXBR4L) U1.W14(VCCR_GXBR4L) U1.W36(VCCR_GXBL1L) U1.W37(VCCR_GXBL1L) U1.W38(VCCR_GXBL1L) U1.W39(VCCR_GXBL1M) U1.W40(VCCR_GXBL1M) U1.W41(VCCR_GXBL1M) ; also on sheet 31 40 45
S10_VCCRAM: U1.AK15(VCCERAM) U1.AK35(VCCERAM) U1.AL15(VCCERAM) U1.AL16(VCCERAM) U1.AL34(VCCERAM) U1.AL35(VCCERAM) U1.AM15(VCCERAM) U1.AM20(VCCERAM) U1.AM23(VCCERAM) U1.AM27(VCCERAM) U1.AM34(VCCERAM) U1.AM35(VCCERAM) U1.AN15(VCCERAM) U1.AN16(VCCERAM) U1.AN31(VCCERAM) U1.AN35(VCCERAM) U1.U35(VCCERAM) U1.V14(VCCERAM) U1.V15(VCCERAM) U1.V16(VCCERAM) U1.V34(VCCERAM) U1.V35(VCCERAM) U1.W15(VCCERAM) U1.W16(VCCERAM) U1.W21(VCCERAM) U1.W23(VCCERAM) U1.W27(VCCERAM) U1.W30(VCCERAM) U1.W33(VCCERAM) U1.W34(VCCERAM) U1.W35(VCCERAM) U1.Y15(VCCERAM) ; also on sheet 31 38 45
S10_VCCT_GXB: U1.AA9(VCCT_GXBR4K) U1.AA10(VCCT_GXBR4K) U1.AA40(VCCT_GXBL1K) U1.AA41(VCCT_GXBL1K) U1.AE9(VCCT_GXBR4E) U1.AE10(VCCT_GXBR4E) U1.AE40(VCCT_GXBL1E) U1.AE41(VCCT_GXBL1E) U1.AJ9(VCCT_GXBR4D) U1.AJ10(VCCT_GXBR4D) U1.AJ12(VCCT_GXBR4F) U1.AJ13(VCCT_GXBR4F) U1.AJ37(VCCT_GXBL1F) U1.AJ38(VCCT_GXBL1F) U1.AJ40(VCCT_GXBL1D) U1.AJ41(VCCT_GXBL1D) U1.AN9(VCCT_GXBR4C) U1.AN10(VCCT_GXBR4C) U1.AN40(VCCT_GXBL1C) U1.AN41(VCCT_GXBL1C) U1.N9(VCCT_GXBR4N) U1.N10(VCCT_GXBR4N) U1.N40(VCCT_GXBL1N) U1.N41(VCCT_GXBL1N) U1.U9(VCCT_GXBR4M) U1.U10(VCCT_GXBR4M) U1.U12(VCCT_GXBR4L) U1.U13(VCCT_GXBR4L) U1.U37(VCCT_GXBL1L) U1.U38(VCCT_GXBL1L) U1.U40(VCCT_GXBL1M) U1.U41(VCCT_GXBL1M) ; also on sheet 31 40 45
S10_VSS_SENSE: R618.2 U1.AF24(GNDSENSE) ; also on sheet 35
SDI_CLK148_DOWN: U1.M20(IO,_LVDS3L_22P,_DQS51) ; also on sheet 18
SDI_CLK148_UP: U1.L20(IO,_LVDS3L_22N,_DQSN51) ; also on sheet 18
SDI_REFCLK_SMA_N: J4.1 U1.T40(REFCLK_GXBL1N_CHBN)
SDI_REFCLK_SMA_P: J3.1 U1.T41(REFCLK_GXBL1N_CHBP)
SDI_RX_N: U1.G42(GXBL1N_RX_CH0N,_GXBL1N_REFCLK0N) ; also on sheet 28
SDI_RX_P: U1.G43(GXBL1N_RX_CH0P,_GXBL1N_REFCLK0P) ; also on sheet 28
SDI_TX_N: U1.G46(GXBL1N_TX_CH1N) ; also on sheet 28
SDI_TX_P: U1.G47(GXBL1N_TX_CH1P) ; also on sheet 28
SMA_CLKOUT_N: J1.1 U1.G23(IO,_PLL_3I_CLKOUT0N,_LVDS3I_15N,_DQ62)
SMA_CLKOUT_P: J2.1 U1.H23(IO,_PLL_3I_CLKOUT0P,_PLL_3I_CLKOUT0,_PLL_3I_FBP,_PLL_3I_FB0,_LVDS3I_15P,_DQ62)
TDIODE_N: U1.C30(DNU2) ; also on sheet 32
TDIODE_P: U1.C31(DNU1) ; also on sheet 32
TSENSE_ALERTn_1.8V: U1.T21(IO,_LVDS3I_2N,_DQ60) ; also on sheet 19
USER_DIPSW0: U1.H18(IO,_LVDS3L_17N,_DQ50) ; also on sheet 29
USER_DIPSW1: U1.G18(IO,_LVDS3L_17P,_DQ50) ; also on sheet 29
USER_DIPSW2: U1.H20(IO,_LVDS3L_18N,_DQ50) ; also on sheet 29
USER_DIPSW3: U1.G20(IO,_LVDS3L_18P,_DQ50) ; also on sheet 29
USER_LED_G0: U1.B19(IO,_LVDS3L_6N,_DQ48) ; also on sheet 29
USER_LED_G1: U1.E17(IO,_LVDS3L_7N,_DQ49) ; also on sheet 29
USER_LED_G2: U1.D18(IO,_LVDS3L_8N,_DQ49) ; also on sheet 29
USER_LED_G3: U1.D19(IO,_LVDS3L_9N,_DQ49) ; also on sheet 29
USER_LED_R0: U1.B18(IO,_LVDS3L_6P,_DQ48) ; also on sheet 29
USER_LED_R1: U1.F17(IO,_LVDS3L_7P,_DQ49) ; also on sheet 29
USER_LED_R2: U1.E18(IO,_LVDS3L_8P,_DQ49) ; also on sheet 29
USER_LED_R3: U1.E19(IO,_LVDS3L_9P,_DQ49) ; also on sheet 29
USER_PB0: U1.B20(IO,_LVDS3L_1N,_DQ48) ; also on sheet 29
USER_PB1: U1.A19(IO,_LVDS3L_1P,_DQ48) ; also on sheet 29
USER_PB2: U1.B17(IO,_LVDS3L_2N,_DQ48) ; also on sheet 29
VREF_FMCA: U1.AP19(VREFB3CN0) U1.AU18(VREFB3BN0) ; also on sheet 25 45
N18107257: R35.2 U1.M23(IO,_RZQ_3I,_LVDS3I_11P,_DQ61)
N18107312: R38.1 U1.E21(IO,_RZQ_3L,_LVDS3L_11P,_DQ49)
N18118440: R36.1 U1.L15(IO,_RZQ_3K,_LVDS3K_11P,_DQ53)
N19188131: C859.1 R5364.1 R5371.2 U1.AG24(VCCLSENSE)
N19308960: R37.1 U1.C18(IO,_LVDS3L_4N,_DQSN48)
N20654580: R608.1 U1.L11(IO,_RZQ_3J,_LVDS3J_11P,_DQ57)

Not connected (* = marked no-connect by the designer): U1 A12(IO,_LVDS3K_19N,_DQ55)* A14(IO,_LVDS3K_17P,_DQ54)* A15(IO,_LVDS3K_17N,_DQ54)* A16(IO,_PLL_3K_CLKOUT0P,_PLL_3K_CLKOUT0,_PLL_3K_FBP,_PLL_3K_FB0,_LVDS3K_15P,_DQ54)* A22(IO,_LVDS3L_5P,_DQ48)* A24(IO,_LVDS3I_19N,_DQ63)* A25(IO,_LVDS3I_21P,_DQ63)* A26(IO,_LVDS3I_21N,_DQ63)* A27(NC6)* A29(NC7)* A30(NC4)* A31(NC39)* A32(NC36)* A34(NC32)* A48(DNU8)* AA3(GXBR4K_TX_CH3P)* AA4(GXBR4K_TX_CH3N)* AB1(GXBR4K_TX_CH4P)* AB2(GXBR4K_TX_CH4N)* AC3(GXBR4K_TX_CH1P)* AC4(GXBR4K_TX_CH1N)* AD1(GXBR4K_TX_CH2P)* AD2(GXBR4K_TX_CH2N)* AD36(DNU5)* AD48(GXBL1K_TX_CH2N)* AD49(GXBL1K_TX_CH2P)* AE3(GXBR4K_TX_CH0P)* AE4(GXBR4K_TX_CH0N)* AE37(DNU6)* AF1(GXBR4F_TX_CH4P)* AF2(GXBR4F_TX_CH4N)* AF13(DNU20)* AF37(DNU19)* AF48(GXBL1F_TX_CH4N)* AF49(GXBL1F_TX_CH4P)* AG3(GXBR4F_TX_CH5P)* AG4(GXBR4F_TX_CH5N)* AG13(DNU18)* AG37(DNU17)* AG46(GXBL1F_TX_CH5N)* AG47(GXBL1F_TX_CH5P)* AH1(GXBR4F_TX_CH2P)* AH2(GXBR4F_TX_CH2N)* AJ3(GXBR4F_TX_CH3P)* AJ4(GXBR4F_TX_CH3N)* AK1(GXBR4F_TX_CH0P)* AK2(GXBR4F_TX_CH0N)* AL3(GXBR4F_TX_CH1P)* AL4(GXBR4F_TX_CH1N)* AM1(GXBR4E_TX_CH5P)* AM2(GXBR4E_TX_CH5N)* AM48(GXBL1E_TX_CH5N)* AM49(GXBL1E_TX_CH5P)* AN3(GXBR4E_TX_CH4P)* AN4(GXBR4E_TX_CH4N)* AN46(GXBL1E_TX_CH4N)* AN47(GXBL1E_TX_CH4P)* AW23(DNU15)* B1(DNU10)* B5(GXBR4N_TX_CH5P)* B6(GXBR4N_TX_CH5N)* B12(IO,_LVDS3K_19P,_DQ55)* B13(IO,_LVDS3K_16N,_DQSN54)* B14(IO,_LVDS3K_16P,_DQS54)* B15(IO,_PLL_3K_CLKOUT0N,_LVDS3K_15N,_DQ54)* B23(IO,_LVDS3I_23N,_DQ63)* B24(IO,_LVDS3I_19P,_DQ63)* B28(NC48)* B29(NC43)* B30(NC11)* B32(NC22)* B33(NC30)* B34(NC19)* B44(GXBL1N_TX_CH5N)* B45(GXBL1N_TX_CH5P)* BF24(DNU13)* BF25(DNU16)* BG24(DNU12)* BH23(DNU14)* BH38(DNU4)* BJ2(DNU9)* BJ24(DNU11)* BJ38(DNU3)* BJ48(DNU7)* C3(GXBR4N_TX_CH4P)* C4(GXBR4N_TX_CH4N)* C12(IO,_LVDS3K_21N,_DQ55)* C13(IO,_LVDS3K_21P,_DQ55)* C15(IO,_LVDS3K_14P,_DQ54)* C16(IO,_LVDS3K_18P,_DQ54)* C17(IO,_LVDS3L_4P,_DQS48)* C20(IO,_PLL_3L_CLKOUT1N,_LVDS3L_10N,_DQSN49)* C21(IO,_CLK_3L_1N,_LVDS3L_12N,_DQ49)* C22(IO,_CLK_3L_1P,_LVDS3L_12P,_DQ49)* C23(IO,_LVDS3I_23P,_DQ63)* C28(NC26)* C32(NC5)* C33(NC2)* C46(GXBL1N_TX_CH4N)* C47(GXBL1N_TX_CH4P)* D1(GXBR4N_TX_CH2P)* D2(GXBR4N_TX_CH2N)* D10(IO,_LVDS3J_3N,_DQ56)* D11(IO,_LVDS3J_3P,_DQ56)* D13(IO,_LVDS3K_23N,_DQ55)* D14(IO,_LVDS3K_20N,_DQ55)* D15(IO,_LVDS3K_14N,_DQ54)* D16(IO,_LVDS3K_18N,_DQ54)* D20(IO,_PLL_3L_CLKOUT1P,_PLL_3L_CLKOUT1,_PLL_3L_FBN,_LVDS3L_10P,_DQS49)* D21(IO,_LVDS3L_11N,_DQ49)* D23(IO,_LVDS3I_22N,_DQSN63)* D24(IO,_LVDS3I_22P,_DQS63)* D28(NC46)* D29(NC12)* D30(NC3)* D31(NC41)* D33(NC45)* D48(GXBL1N_TX_CH2N)* D49(GXBL1N_TX_CH2P)* E3(GXBR4N_TX_CH3P)* E4(GXBR4N_TX_CH3N)* E10(IO,_LVDS3J_5P,_DQ56)* E11(IO,_LVDS3J_1N,_DQ56)* E12(IO,_LVDS3J_6P,_DQ56)* E13(IO,_LVDS3K_23P,_DQ55)* E14(IO,_LVDS3K_20P,_DQ55)* E16(IO,_CLK_3K_0P,_LVDS3K_13P,_DQ54)* E22(IO,_LVDS3I_20P,_DQ63)* E23(IO,_LVDS3I_24N,_DQ63)* E24(IO,_LVDS3I_24P,_DQ63)* E28(NC18)* E29(NC1)* E31(NC20)* E32(NC10)* E33(NC8)* E46(GXBL1N_TX_CH3N)* E47(GXBL1N_TX_CH3P)* F1(GXBR4N_TX_CH0P)* F2(GXBR4N_TX_CH0N)* F10(IO,_LVDS3J_5N,_DQ56)* F11(IO,_LVDS3J_1P,_DQ56)* F12(IO,_LVDS3J_6N,_DQ56)* F14(IO,_LVDS3K_22N,_DQSN55)* F15(IO,_LVDS3K_9N,_DQ53)* F16(IO,_CLK_3K_0N,_LVDS3K_13N,_DQ54)* F19(IO,_LVDS3L_14N,_DQ50)* F20(IO,_LVDS3L_16P,_DQS50)* F21(IO,_LVDS3L_16N,_DQSN50)* F22(IO,_LVDS3I_20N,_DQ63)* F24(IO,_LVDS3I_14P,_DQ62)* F29(NC9)* F30(NC16)* F31(NC13)* F32(NC34)* F48(GXBL1N_TX_CH0N)* F49(GXBL1N_TX_CH0P)* G3(GXBR4N_TX_CH1P)* G4(GXBR4N_TX_CH1N)* G10(IO,_LVDS3J_2N,_DQ56)* G12(IO,_LVDS3J_4N,_DQSN56)* G13(IO,_LVDS3K_24P,_DQ55)* G14(IO,_LVDS3K_22P,_DQS55)* G15(IO,_LVDS3K_9P,_DQ53)* G17(IO,_LVDS3K_8P,_DQ53)* G19(IO,_LVDS3L_14P,_DQ50)* G22(IO,_LVDS3I_18P,_DQ62)* G24(IO,_LVDS3I_14N,_DQ62)* G28(NC15)* G29(NC23)* G30(NC25)* G32(NC35)* H1(GXBR4M_TX_CH4P)* H2(GXBR4M_TX_CH4N)* H10(IO,_LVDS3J_2P,_DQ56)* H11(IO,_LVDS3J_7P,_DQ57)* H12(IO,_LVDS3J_4P,_DQS56)* H13(IO,_LVDS3K_24N,_DQ55)* H15(IO,_PLL_3K_CLKOUT1P,_PLL_3K_CLKOUT1,_PLL_3K_FBN,_LVDS3K_10P,_DQS53)* H16(IO,_CLK_3K_1N,_LVDS3K_12N,_DQ53)* H17(IO,_LVDS3K_8N,_DQ53)* H21(IO,_LVDS3L_19N,_DQ51)* H22(IO,_LVDS3I_18N,_DQ62)* H28(NC24)* H30(NC40)* H31(NC29)* H32(NC42)* H48(GXBL1M_TX_CH4N)* H49(GXBL1M_TX_CH4P)* J3(GXBR4M_TX_CH5P)* J4(GXBR4M_TX_CH5N)* J10(IO,_LVDS3J_9P,_DQ57)* J11(IO,_LVDS3J_7N,_DQ57)* J13(IO,_CLK_3J_1P,_LVDS3J_12P,_DQ57)* J14(IO,_LVDS3K_7N,_DQ53)* J15(IO,_PLL_3K_CLKOUT1N,_LVDS3K_10N,_DQSN53)* J16(IO,_CLK_3K_1P,_LVDS3K_12P,_DQ53)* J18(IO,_PLL_3L_CLKOUT0P,_PLL_3L_CLKOUT0,_PLL_3L_FBP,_PLL_3L_FB0,_LVDS3L_15P,_DQ50)* J21(IO,_LVDS3L_19P,_DQ51)* J23(IO,_LVDS3I_16P,_DQS62)* J24(IO,_LVDS3I_17N,_DQ62)* J28(NC17)* J29(NC27)* J30(NC38)* J31(NC44)* J46(GXBL1M_TX_CH5N)* J47(GXBL1M_TX_CH5P)* K1(GXBR4M_TX_CH2P)* K2(GXBR4M_TX_CH2N)* K10(IO,_LVDS3J_9N,_DQ57)* K11(IO,_LVDS3J_8N,_DQ57)* K12(IO,_LVDS3J_8P,_DQ57)* K13(IO,_CLK_3J_1N,_LVDS3J_12N,_DQ57)* K14(IO,_LVDS3K_7P,_DQ53)* K16(IO,_LVDS3K_3N,_DQ52)* K17(IO,_LVDS3K_4N,_DQSN52)* K18(IO,_PLL_3L_CLKOUT0N,_LVDS3L_15N,_DQ50)* K19(IO,_LVDS3L_20P,_DQ51)* K22(IO,_LVDS3I_8P,_DQ61)* K23(IO,_LVDS3I_16N,_DQSN62)* K24(IO,_LVDS3I_17P,_DQ62)* K28(NC28)* K29(NC33)* K31(NC47)* K48(GXBL1M_TX_CH2N)* K49(GXBL1M_TX_CH2P)* L3(GXBR4M_TX_CH3P)* L4(GXBR4M_TX_CH3N)* L10(IO,_LVDS3J_11N,_DQ57)* L12(IO,_PLL_3J_CLKOUT1P,_PLL_3J_CLKOUT1,_PLL_3J_FBN,_LVDS3J_10P,_DQS57)* L14(IO,_LVDS3K_11N,_DQ53)* L16(IO,_LVDS3K_3P,_DQ52)* L17(IO,_LVDS3K_4P,_DQS52)* L19(IO,_LVDS3L_20N,_DQ51)* L22(IO,_LVDS3I_8N,_DQ61)* L24(IO,_CLK_3I_0N,_LVDS3I_13N,_DQ62)* L46(GXBL1M_TX_CH3N)* L47(GXBL1M_TX_CH3P)* M1(GXBR4M_TX_CH0P)* M2(GXBR4M_TX_CH0N)* M12(IO,_PLL_3J_CLKOUT1N,_LVDS3J_10N,_DQSN57)* M13(IO,_LVDS3J_14N,_DQ58)* M14(IO,_LVDS3J_14P,_DQ58)* M15(IO,_LVDS3K_1N,_DQ52)* M17(IO,_LVDS3K_6P,_DQ52)* M18(IO,_LVDS3K_6N,_DQ52)* M22(IO,_LVDS3I_7P,_DQ61)* M24(IO,_CLK_3I_0P,_LVDS3I_13P,_DQ62)* M48(GXBL1M_TX_CH0N)* M49(GXBL1M_TX_CH0P)* N3(GXBR4M_TX_CH1P)* N4(GXBR4M_TX_CH1N)* N13(IO,_CLK_3J_0N,_LVDS3J_13N,_DQ58)* N15(IO,_LVDS3K_1P,_DQ52)* N16(IO,_LVDS3K_5P,_DQ52)* N17(IO,_LVDS3K_5N,_DQ52)* N18(IO,_LVDS3K_2N,_DQ52)* N22(IO,_LVDS3I_7N,_DQ61)* N23(IO,_LVDS3I_11N,_DQ61)* N30(NC31)* N46(GXBL1M_TX_CH1N)* N47(GXBL1M_TX_CH1P)* P1(GXBR4L_TX_CH4P)* P2(GXBR4L_TX_CH4N)* P12(IO,_LVDS3J_16P,_DQS58)* P13(IO,_LVDS3J_16N,_DQSN58)* P14(IO,_CLK_3J_0P,_LVDS3J_13P,_DQ58)* P15(IO,_PLL_3J_CLKOUT0N,_LVDS3J_15N,_DQ58)* P16(IO,_PLL_3J_CLKOUT0P,_PLL_3J_CLKOUT0,_PLL_3J_FBP,_PLL_3J_FB0,_LVDS3J_15P,_DQ58)* P18(IO,_LVDS3K_2P,_DQ52)* P23(IO,_LVDS3I_9P,_DQ61)* P24(IO,_PLL_3I_CLKOUT1P,_PLL_3I_CLKOUT1,_PLL_3I_FBN,_LVDS3I_10P,_DQS61)* P29(NC21)* P30(NC37)* P48(GXBL1L_TX_CH4N)* P49(GXBL1L_TX_CH4P)* R3(GXBR4L_TX_CH5P)* R4(GXBR4L_TX_CH5N)* R13(IO,_LVDS3J_18P,_DQ58)* R14(IO,_LVDS3J_18N,_DQ58)* R16(IO,_LVDS3J_17N,_DQ58)* R17(IO,_LVDS3J_17P,_DQ58)* R18(IO,_LVDS3J_20N,_DQ59)* R19(IO,_LVDS3J_20P,_DQ59)* R22(IO,_LVDS3I_5N,_DQ60)* R23(IO,_LVDS3I_9N,_DQ61)* R24(IO,_PLL_3I_CLKOUT1N,_LVDS3I_10N,_DQSN61)* R29(NC14)* R46(GXBL1L_TX_CH5N)* R47(GXBL1L_TX_CH5P)* T1(GXBR4L_TX_CH3P)* T2(GXBR4L_TX_CH3N)* T15(IO,_LVDS3J_24P,_DQ59)* T16(IO,_LVDS3J_24N,_DQ59)* T17(IO,_LVDS3J_22N,_DQSN59)* T19(IO,_LVDS3J_19N,_DQ59)* T20(IO,_LVDS3I_4P,_DQS60)* T22(IO,_LVDS3I_5P,_DQ60)* T24(IO,_CLK_3I_1N,_LVDS3I_12N,_DQ61)* T48(GXBL1L_TX_CH3N)* T49(GXBL1L_TX_CH3P)* U3(GXBR4L_TX_CH2P)* U4(GXBR4L_TX_CH2N)* U17(IO,_LVDS3J_22P,_DQS59)* U18(IO,_LVDS3J_23N,_DQ59)* U19(IO,_LVDS3J_19P,_DQ59)* U20(IO,_LVDS3I_4N,_DQSN60)* U22(IO,_LVDS3I_6P,_DQ60)* U23(IO,_LVDS3I_6N,_DQ60)* U24(IO,_CLK_3I_1P,_LVDS3I_12P,_DQ61)* U46(GXBL1L_TX_CH2N)* U47(GXBL1L_TX_CH2P)* V1(GXBR4L_TX_CH1P)* V2(GXBR4L_TX_CH1N)* V17(IO,_LVDS3J_21P,_DQ59)* V18(IO,_LVDS3J_23P,_DQ59)* V23(IO,_LVDS3I_3N,_DQ60)* V24(IO,_LVDS3I_3P,_DQ60)* V48(GXBL1L_TX_CH1N)* V49(GXBL1L_TX_CH1P)* W3(GXBR4K_TX_CH5P)* W4(GXBR4K_TX_CH5N)* W18(IO,_LVDS3J_21N,_DQ59)* W46(GXBL1K_TX_CH5N)* W47(GXBL1K_TX_CH5P)* Y1(GXBR4L_TX_CH0P)* Y2(GXBR4L_TX_CH0N)* Y48(GXBL1L_TX_CH0N)* Y49(GXBL1L_TX_CH0P)*

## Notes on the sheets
sheet 10
- S10 GX Bank 3I, J, K, L
- 1.8V
- 1.8V
- PUSH BUTTON INTERFACE
- LED INTERFACE
- DIPSWITCH INTERFACE
- 1.8V
- 1.8V
- USER PB, SWITCHES, LEDS
- ARRIA 10 CLOCKS
sheet 11
- S10 GX Xcvr GXBL 1C,D,E,F
- PCIE x16 INTERFACE
- DISPLAYPORT INTERFACE
- PCIE x16
- PCIE x16
- DISPLAY PORT
- PCIE x16
sheet 12
- S10 GX Xcvr GXBL 1K,L,M,N
- QSFP1 INTERFACE
- SDI INTERFACE
- TX1 and TX3 Channels swapped to
  uncross layout routing
- QSFP1
- Not Used
- RX1 and RX3 Channels swapped to
  uncross layout routing
- Not Used
- SDI
- Note:
  ---------
  TX1_P/N and RX0_P/N is used
  to avoid coupling issue in
  Arria 10 transceivers (since
  S10 uses A10 transceivers for
  the first silicon tapeout).
sheet 13
- S10 GX Xcvr GXBR 4C,D,E,F
- FMCA INTERFACE
- FMCA
- FMCA
- FMCA
- Not Used
sheet 14
- S10 GX Xcvr GXBR 4K,L,M,N
sheet 15
- S10 GX Power
- These HPS I/O Functions exist
  in SX device only.  They are NC
  on GX device.
- C31/C30 are not recommended for thermal sensing
  purposes.  Refer to the latest pin-out files for
  new pin locations.
- VCCL_HPS
  (SX only)
